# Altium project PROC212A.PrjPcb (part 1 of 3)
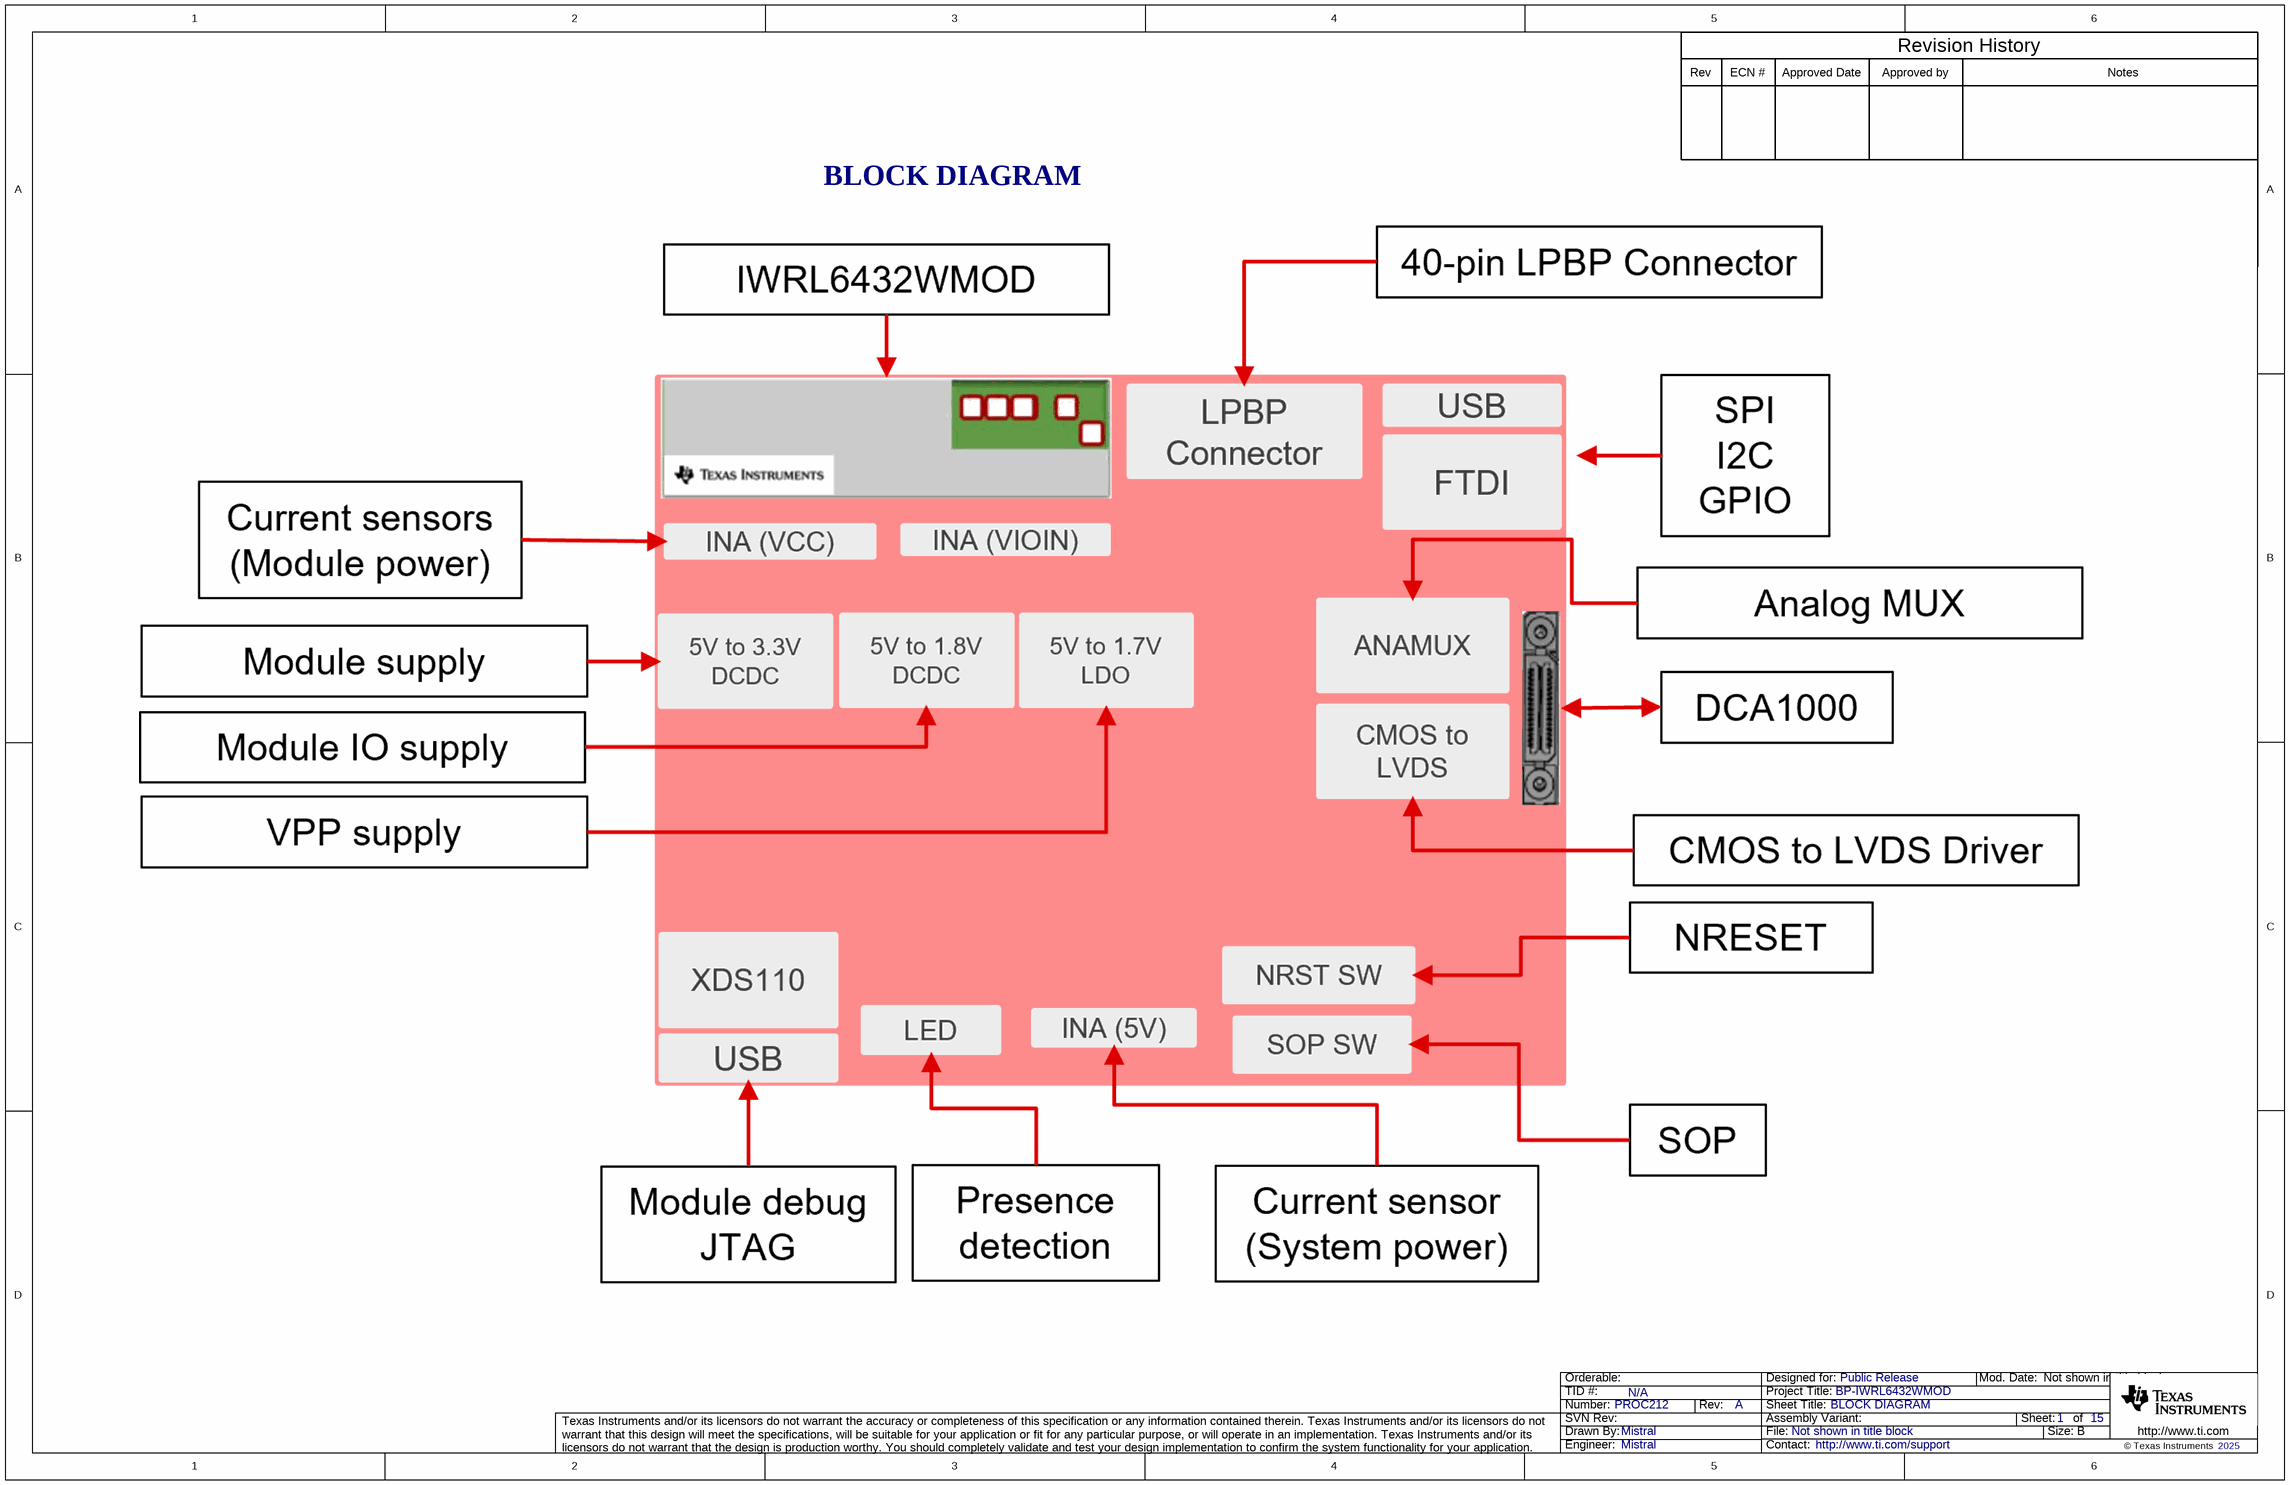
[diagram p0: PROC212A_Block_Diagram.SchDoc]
CopyrightYear: 2025; PCB_Layout: Mistral; PCB_Rev: A; PRJ_Customer: Public Release; PRJ_Engineer: Mistral; PRJ_Number: PROC212; PRJ_Title: BP-IWRL6432WMOD; SCH_Rev: A; TechSupport: http://www.ti.com/support; TID: N/A
15 sheets, 425 parts. Net scope: flat (ports and power ports of the same name join across sheets).
Board file: PROC212A_PCB.PcbDoc
Sheets:
  PROC212A_Block_Diagram.SchDoc
  PROC212A_MUX_Block_Diagram.SchDoc
  PROC212A_Table_Of_Contents.SchDoc
  PROC212A_BP_MMWAVE_MODULE.SchDoc
  PROC212A_USB_DC_JACK_PWR_Switch.SchDoc
  PROC212A_DC_Regulators.SchDoc
  PROC212A_ANALOG_MUX_LVDS_DRIVER.SchDoc
  PROC212A_ANALOG_MUX_SPI.SchDoc
  PROC212A_ANALOG_JTAG_MUX, CAN & SOP_CTRL.SchDoc
  PROC212A_Current_sensors_EPROM.SchDoc
  PROC212A_XDS110_Interface.SchDoc
  PROC212A_FTDI.SchDoc
  PROC212A_Reset_SW_LED_&_PRESENCE_LED.SchDoc
  PROC212A_DCA1000_LP_BP_Connectors.SchDoc
  PROC212A_EVM_Hardware.SchDoc

## Sheet PROC212A_Block_Diagram.SchDoc: BLOCK DIAGRAM
size 431 x 279 mm; Date: Not shown in title block; ApprovedBy: Not shown in title block; CheckedBy: Not shown in title block; Author: Not shown in title block; CompanyName: Not shown in title block; DrawnBy: Mistral; Organization: Not shown in title block; Address1: Not shown in title block; Address2: Not shown in title block; Address3: Not shown in title block; Address4: Not shown in title block; DocumentNumber: 1; Revision: Use project parameter SCH_Rev; SheetNumber: 1; SheetTotal: 15; PageSetup: Record=PageOptions¦CenterHorizontal=True¦CenterVertical=True¦PrintScale=1.00¦XCorrection=1.00¦YCorrection=1.00¦PrintKind=0¦BorderSize=5000000¦LeftOffset=0¦BottomOffset=0¦Orientation=2¦PaperLength=1000¦PaperWidth=1000¦Scale=100¦PaperSource=15¦PrintQuality=600¦MediaType=1¦DitherType=10¦PaperKind=Letter¦PrintScaleMode=1

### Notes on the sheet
- Rev
- ECN #
- Approved Date
- Approved by
- Revision History
- Notes
- BLOCK DIAGRAM

## Sheet PROC212A_MUX_Block_Diagram.SchDoc: MUX BLOCK DIAGRAM
size 431 x 279 mm; Date: Not shown in title block; ApprovedBy: Not shown in title block; CheckedBy: Not shown in title block; Author: Not shown in title block; CompanyName: Not shown in title block; DrawnBy: Mistral; Engineer: Not shown in title block; Organization: Not shown in title block; Address1: Not shown in title block; Address2: Not shown in title block; Address3: Not shown in title block; Address4: Not shown in title block; DocumentNumber: 2; Revision: Use project parameter SCH_Rev; SheetNumber: 2; SheetTotal: 15; PageSetup: Record=PageOptions¦CenterHorizontal=True¦CenterVertical=True¦PrintScale=1.00¦XCorrection=1.00¦YCorrection=1.00¦PrintKind=0¦BorderSize=5000000¦LeftOffset=0¦BottomOffset=0¦Orientation=2¦PaperLength=1000¦PaperWidth=1000¦Scale=100¦PaperSource=15¦PrintQuality=600¦MediaType=1¦DitherType=10¦PaperKind=Letter¦PrintScaleMode=1
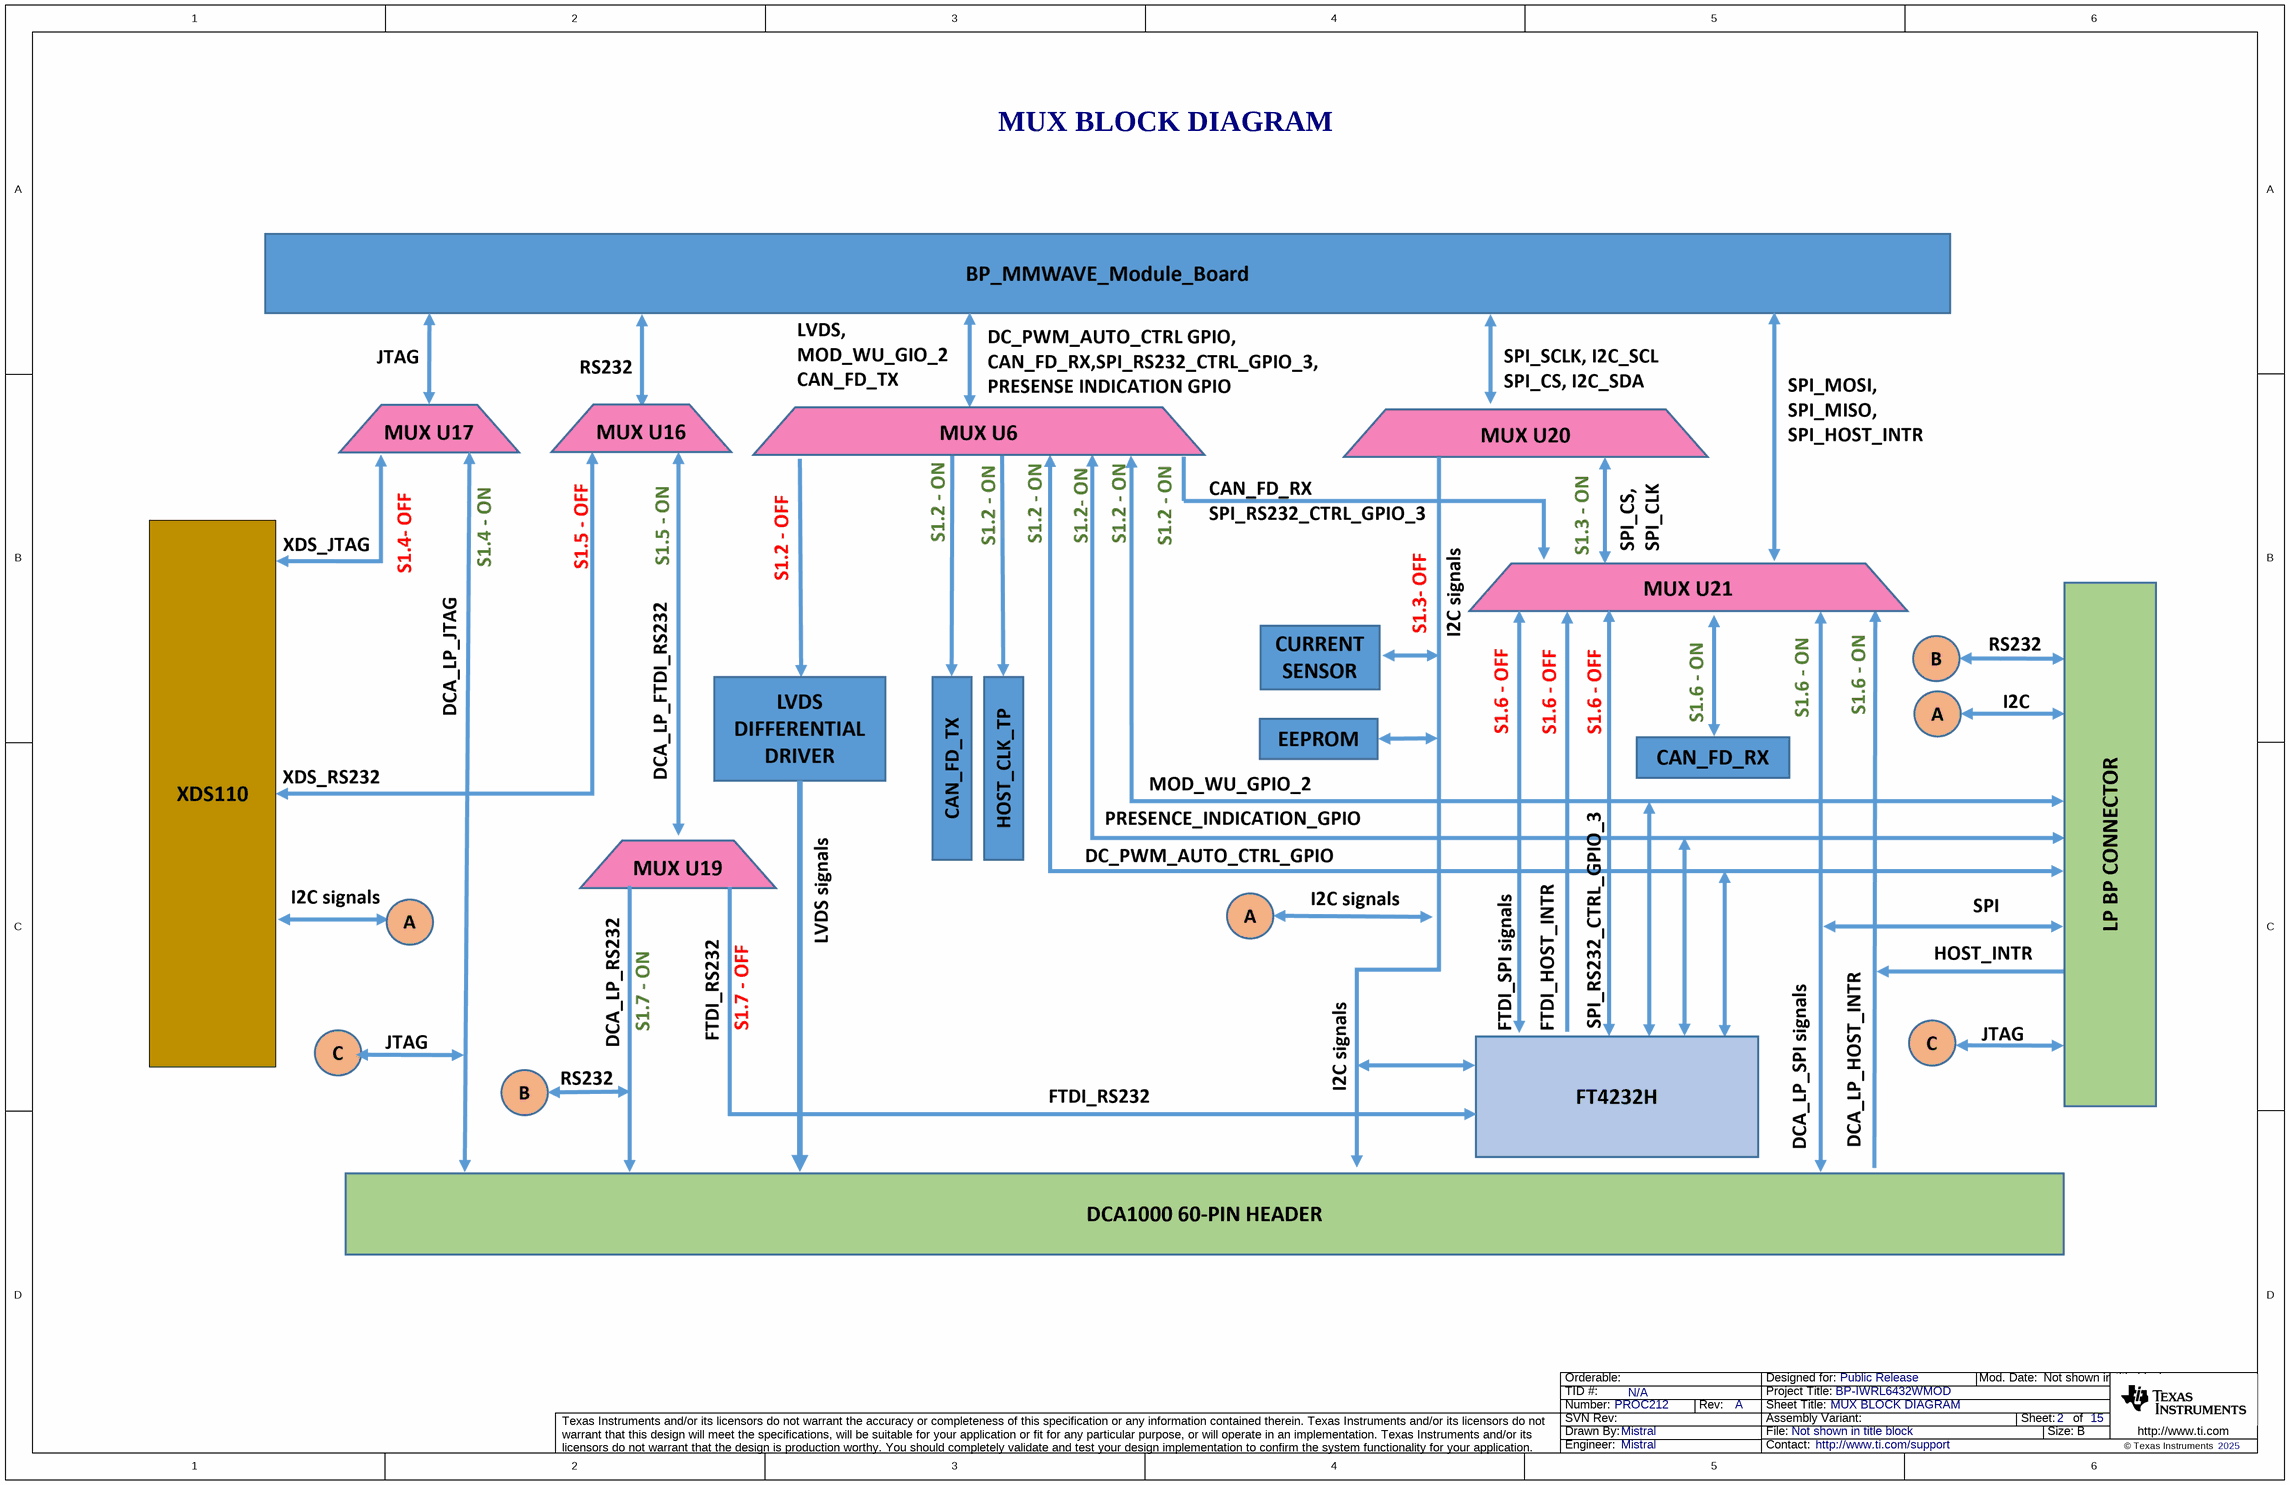
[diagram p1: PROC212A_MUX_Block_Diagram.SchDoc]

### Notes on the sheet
- MUX BLOCK DIAGRAM

## Sheet PROC212A_Table_Of_Contents.SchDoc: TABLE OF CONTENTS
size 431 x 279 mm; Date: Not shown in title block; ApprovedBy: Not shown in title block; CheckedBy: Not shown in title block; Author: Not shown in title block; CompanyName: Not shown in title block; DrawnBy: Mistral; Engineer: Not shown in title block; Organization: Not shown in title block; Address1: Not shown in title block; Address2: Not shown in title block; Address3: Not shown in title block; Address4: Not shown in title block; DocumentNumber: 3; Revision: Use project parameter SCH_Rev; SheetNumber: 3; SheetTotal: 15; PageSetup: Record=PageOptions¦CenterHorizontal=True¦CenterVertical=True¦PrintScale=1.00¦XCorrection=1.00¦YCorrection=1.00¦PrintKind=0¦BorderSize=5000000¦LeftOffset=0¦BottomOffset=0¦Orientation=2¦PaperLength=1000¦PaperWidth=1000¦Scale=100¦PaperSource=15¦PrintQuality=600¦MediaType=1¦DitherType=10¦PaperKind=Letter¦PrintScaleMode=1
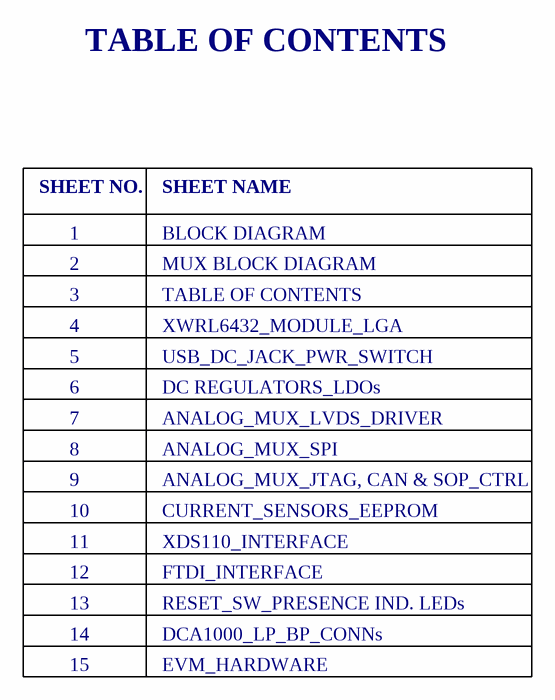
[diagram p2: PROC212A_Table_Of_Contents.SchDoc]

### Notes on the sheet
- TABLE OF CONTENTS
- SHEET NO.
- SHEET NAME
- 1
- 2
- 3
- BLOCK DIAGRAM
- MUX BLOCK DIAGRAM
- 4
- 5
- USB_DC_JACK_PWR_SWITCH
- XWRL6432_MODULE_LGA
- 7
- 8
- 6
- ANALOG_MUX_LVDS_DRIVER
- DC REGULATORS_LDOs
- ANALOG_MUX_SPI
- 9
- 10
- CURRENT_SENSORS_EEPROM
- ANALOG_MUX_JTAG, CAN & SOP_CTRL
- 11
- 12
- 13
- XDS110_INTERFACE
- FTDI_INTERFACE
- RESET_SW_PRESENCE IND. LEDs
- 14
- 15
- DCA1000_LP_BP_CONNs
- EVM_HARDWARE

## Sheet PROC212A_BP_MMWAVE_MODULE.SchDoc: BP_MMWAVE_MODULE_LGA
size 431 x 279 mm; Date: Not shown in title block; ApprovedBy: Not shown in title block; CheckedBy: Not shown in title block; Author: Not shown in title block; CompanyName: Not shown in title block; DrawnBy: Mistral; Engineer: Not shown in title block; Organization: Not shown in title block; Address1: Not shown in title block; Address2: Not shown in title block; Address3: Not shown in title block; Address4: Not shown in title block; DocumentNumber: 4; Revision: Use project parameter SCH_Rev; SheetNumber: 4; SheetTotal: 15; PageSetup: Record=PageOptions¦CenterHorizontal=True¦CenterVertical=True¦PrintScale=1.00¦XCorrection=1.00¦YCorrection=1.00¦PrintKind=0¦BorderSize=5000000¦LeftOffset=0¦BottomOffset=0¦Orientation=2¦PaperLength=1000¦PaperWidth=1000¦Scale=100¦PaperSource=15¦PrintQuality=600¦MediaType=1¦DitherType=10¦PaperKind=Letter¦PrintScaleMode=1
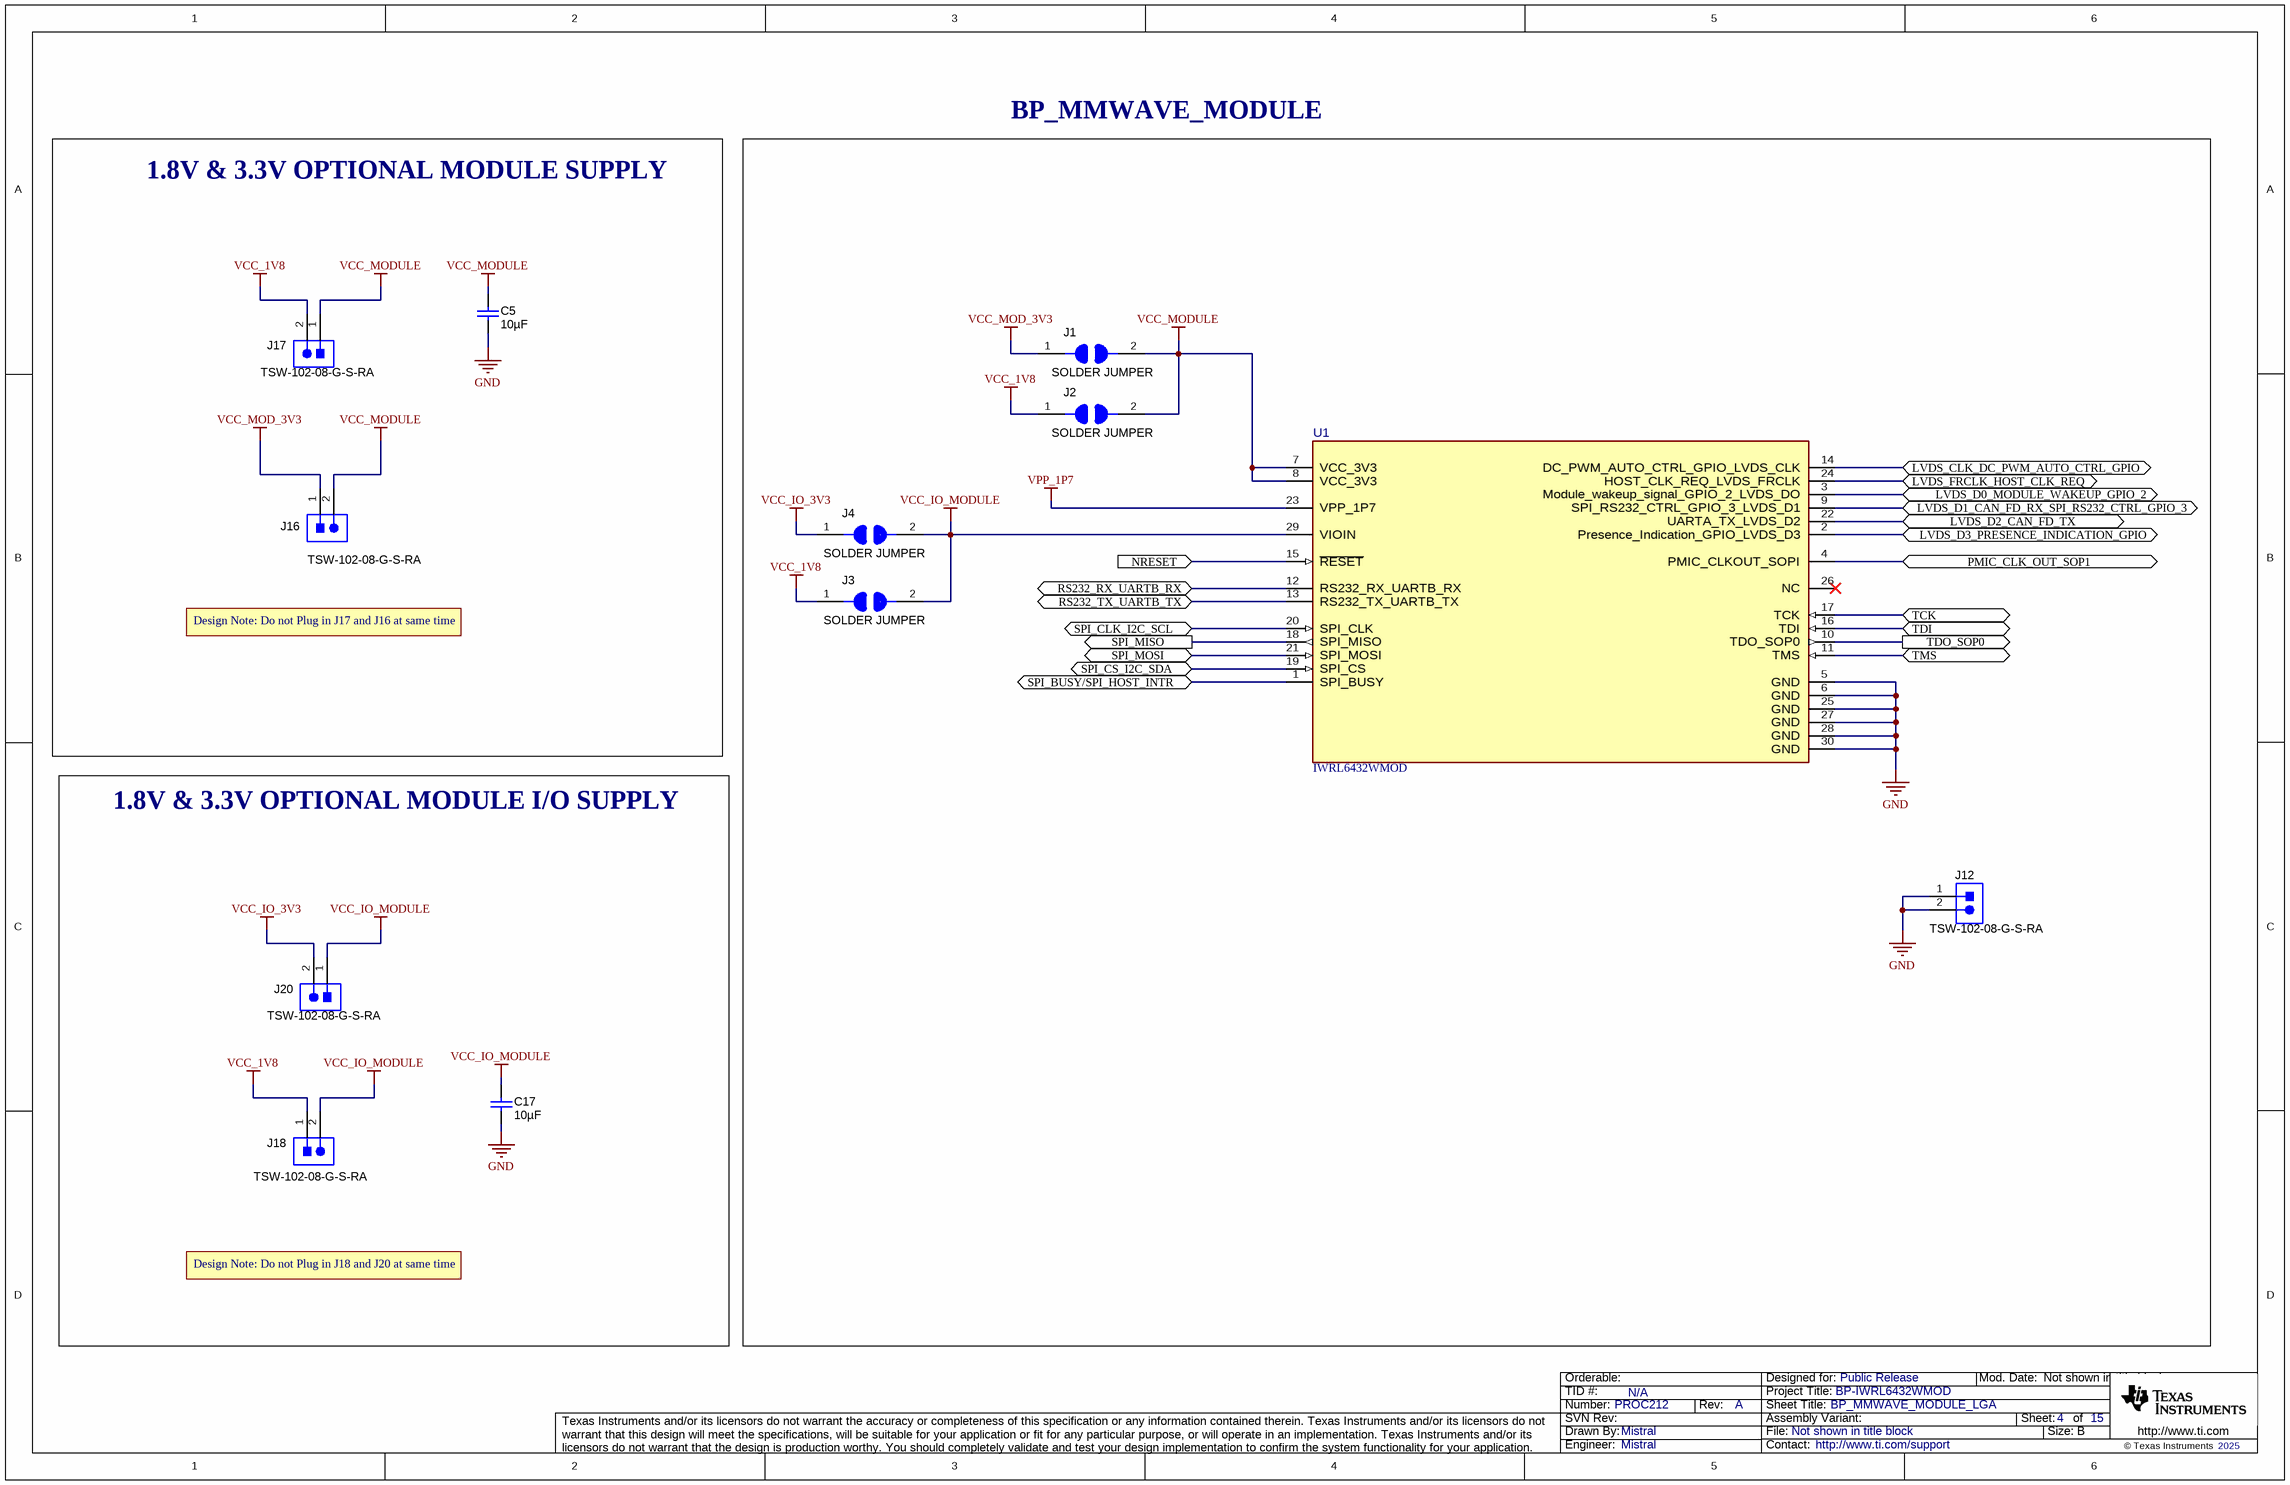
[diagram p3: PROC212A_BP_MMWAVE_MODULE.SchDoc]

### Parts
C5  Cap_F: 10µF  [0603]  (hidden comment: GRM188Z71A106MA73D)
C17  Cap_F: 10µF  [0603]  (hidden comment: GRM188Z71A106MA73D)
J1  SOLDER JUMPER  [SolderJumper]
J2  SOLDER JUMPER  [SolderJumper]
J3  SOLDER JUMPER  [SolderJumper]
J4  SOLDER JUMPER  [SolderJumper]
J12  TSW-102-08-G-S-RA  [TSW-102-08-G-S-RA]
J16  TSW-102-08-G-S-RA  [TSW-102-08-G-S-RA]
J17  TSW-102-08-G-S-RA  [TSW-102-08-G-S-RA]
J18  TSW-102-08-G-S-RA  [TSW-102-08-G-S-RA]
J20  TSW-102-08-G-S-RA  [TSW-102-08-G-S-RA]
U1  IWRL6432WMOD  [MBB0030A-MFG]

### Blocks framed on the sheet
1.8V & 3.3V OPTIONAL MODULE SUPPLY: C5 J16 J17
BP_MMWAVE_MODULE: J1-J4 J12 U1
1.8V & 3.3V OPTIONAL MODULE I/O SUPPLY: C17 J18 J20

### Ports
LVDS_CLK_DC_PWM_AUTO_CTRL_GPIO (bidir), LVDS_D0_MODULE_WAKEUP_GPIO_2 (bidir), LVDS_D1_CAN_FD_RX_SPI_RS232_CTRL_GPIO_3 (bidir), LVDS_D2_CAN_FD_TX (bidir), LVDS_D3_PRESENCE_INDICATION_GPIO (bidir), LVDS_FRCLK_HOST_CLK_REQ (bidir), NRESET (in), PMIC_CLK_OUT_SOP1 (bidir), RS232_RX_UARTB_RX (bidir), RS232_TX_UARTB_TX (bidir), SPI_BUSY/SPI_HOST_INTR (bidir), SPI_CLK_I2C_SCL (bidir), SPI_CS_I2C_SDA (bidir), SPI_MISO (out), SPI_MOSI (bidir), TCK (bidir), TDI (bidir), TDO_SOP0 (out), TMS (bidir)

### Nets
GND: C5.2 C17.2 J12.1 J12.2 U1.5(GND) U1.6(GND) U1.25(GND) U1.27(GND) U1.28(GND) U1.30(GND)
VCC_1V8: J2.1 J3.1 J17.2 J18.1
VCC_IO_3V3: J4.1 J20.2
VCC_IO_MODULE: C17.1 J3.2 J4.2 J18.2 J20.1 U1.29(VIOIN)
VCC_MOD_3V3: J1.1 J16.1
VCC_MODULE: C5.1 J1.2 J2.2 J16.2 J17.1 U1.7(VCC_3V3) U1.8(VCC_3V3)
VPP_1P7: U1.23(VPP_1P7)
LVDS_CLK_DC_PWM_AUTO_CTRL_GPIO: U1.14(DC_PWM_AUTO_CTRL_GPIO_LVDS_CLK) ; port LVDS_CLK_DC_PWM_AUTO_CTRL_GPIO
LVDS_D0_MODULE_WAKEUP_GPIO_2: U1.3(Module_wakeup_signal_GPIO_2_LVDS_DO) ; port LVDS_D0_MODULE_WAKEUP_GPIO_2
LVDS_D1_CAN_FD_RX_SPI_RS232_CTRL_GPIO_3: U1.9(SPI_RS232_CTRL_GPIO_3_LVDS_D1) ; port LVDS_D1_CAN_FD_RX_SPI_RS232_CTRL_GPIO_3
LVDS_D2_CAN_FD_TX: U1.22(UARTA_TX_LVDS_D2) ; port LVDS_D2_CAN_FD_TX
LVDS_D3_PRESENCE_INDICATION_GPIO: U1.2(Presence_Indication_GPIO_LVDS_D3) ; port LVDS_D3_PRESENCE_INDICATION_GPIO
LVDS_FRCLK_HOST_CLK_REQ: U1.24(HOST_CLK_REQ_LVDS_FRCLK) ; port LVDS_FRCLK_HOST_CLK_REQ
NRESET: U1.15(~{RESET}) ; port NRESET
PMIC_CLK_OUT_SOP1: U1.4(PMIC_CLKOUT_SOPI) ; port PMIC_CLK_OUT_SOP1
RS232_RX_UARTB_RX: U1.12(RS232_RX_UARTB_RX) ; port RS232_RX_UARTB_RX
RS232_TX_UARTB_TX: U1.13(RS232_TX_UARTB_TX) ; port RS232_TX_UARTB_TX
SPI_BUSY/SPI_HOST_INTR: U1.1(SPI_BUSY) ; port SPI_BUSY/SPI_HOST_INTR
SPI_CLK_I2C_SCL: U1.20(SPI_CLK) ; port SPI_CLK_I2C_SCL
SPI_CS_I2C_SDA: U1.19(SPI_CS) ; port SPI_CS_I2C_SDA
SPI_MISO: U1.18(SPI_MISO) ; port SPI_MISO
SPI_MOSI: U1.21(SPI_MOSI) ; port SPI_MOSI
TCK: U1.17(TCK) ; port TCK
TDI: U1.16(TDI) ; port TDI
TDO_SOP0: U1.10(TDO_SOP0) ; port TDO_SOP0
TMS: U1.11(TMS) ; port TMS

Not connected (* = marked no-connect by the designer): U1 26(NC)*

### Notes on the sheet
- Design Note: Do not Plug in J17 and J16 at same time
- Design Note: Do not Plug in J18 and J20 at same time

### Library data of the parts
C5 C17 = CMP-0007497-5: CAP, CERM, 10 uF, 10 V, +/- 20%, X7R, 0603; Manufacturer: MuRata; TaMin_C: -55°C; Polarized: N; SizeAreaWB_mm2: 4.68; Value1: Unknown; U/M: EA; Value: 10uF; TaMax_C: 125°C; SizeZ_mm: 1; SizeX_mm: 1.6; SizeY_mm: 0.8; Value2: 10V; SizeArea_mm2: 1.28; AEC Category: Q200
J1-J4 = CMP-0080367-2: Solder Jumper, SMT; Manufacturer: NA
J12 J16-J18 J20 = CMP-0055976-1: Header, 100mil, 2x1, Gold, R/A, TH; Manufacturer: Samtec; Cert_VDE: N; CNHeader: FALSE; Current_A: 6.3A; Green_Lifecycle: Active; Gender: Male; Cert_CSA: Y; Green_REACh: Passed; Voltage_V: 550V; Row_Count: 1; Pitch_mm: 2.54
U1 = CMP-0125875-3: Manufacturer: Texas Instruments; SizeZ_mm: 3.75mm; AEC Category: Q200; CompType: IC

## Sheet PROC212A_USB_DC_JACK_PWR_Switch.SchDoc: USB_DC_JACK_PWR_SWITCH
size 431 x 279 mm; Date: Not shown in title block; ApprovedBy: Not shown in title block; CheckedBy: Not shown in title block; Author: Not shown in title block; CompanyName: Not shown in title block; DrawnBy: Mistral; Engineer: Not shown in title block; Organization: Not shown in title block; Address1: Not shown in title block; Address2: Not shown in title block; Address3: Not shown in title block; Address4: Not shown in title block; DocumentNumber: 5; Revision: Use project parameter SCH_Rev; SheetNumber: 5; SheetTotal: 15; PageSetup: Record=PageOptions¦CenterHorizontal=True¦CenterVertical=True¦PrintScale=1.00¦XCorrection=1.00¦YCorrection=1.00¦PrintKind=0¦BorderSize=5000000¦LeftOffset=0¦BottomOffset=0¦Orientation=2¦PaperLength=1000¦PaperWidth=1000¦Scale=100¦PaperSource=15¦PrintQuality=600¦MediaType=1¦DitherType=10¦PaperKind=Letter¦PrintScaleMode=1
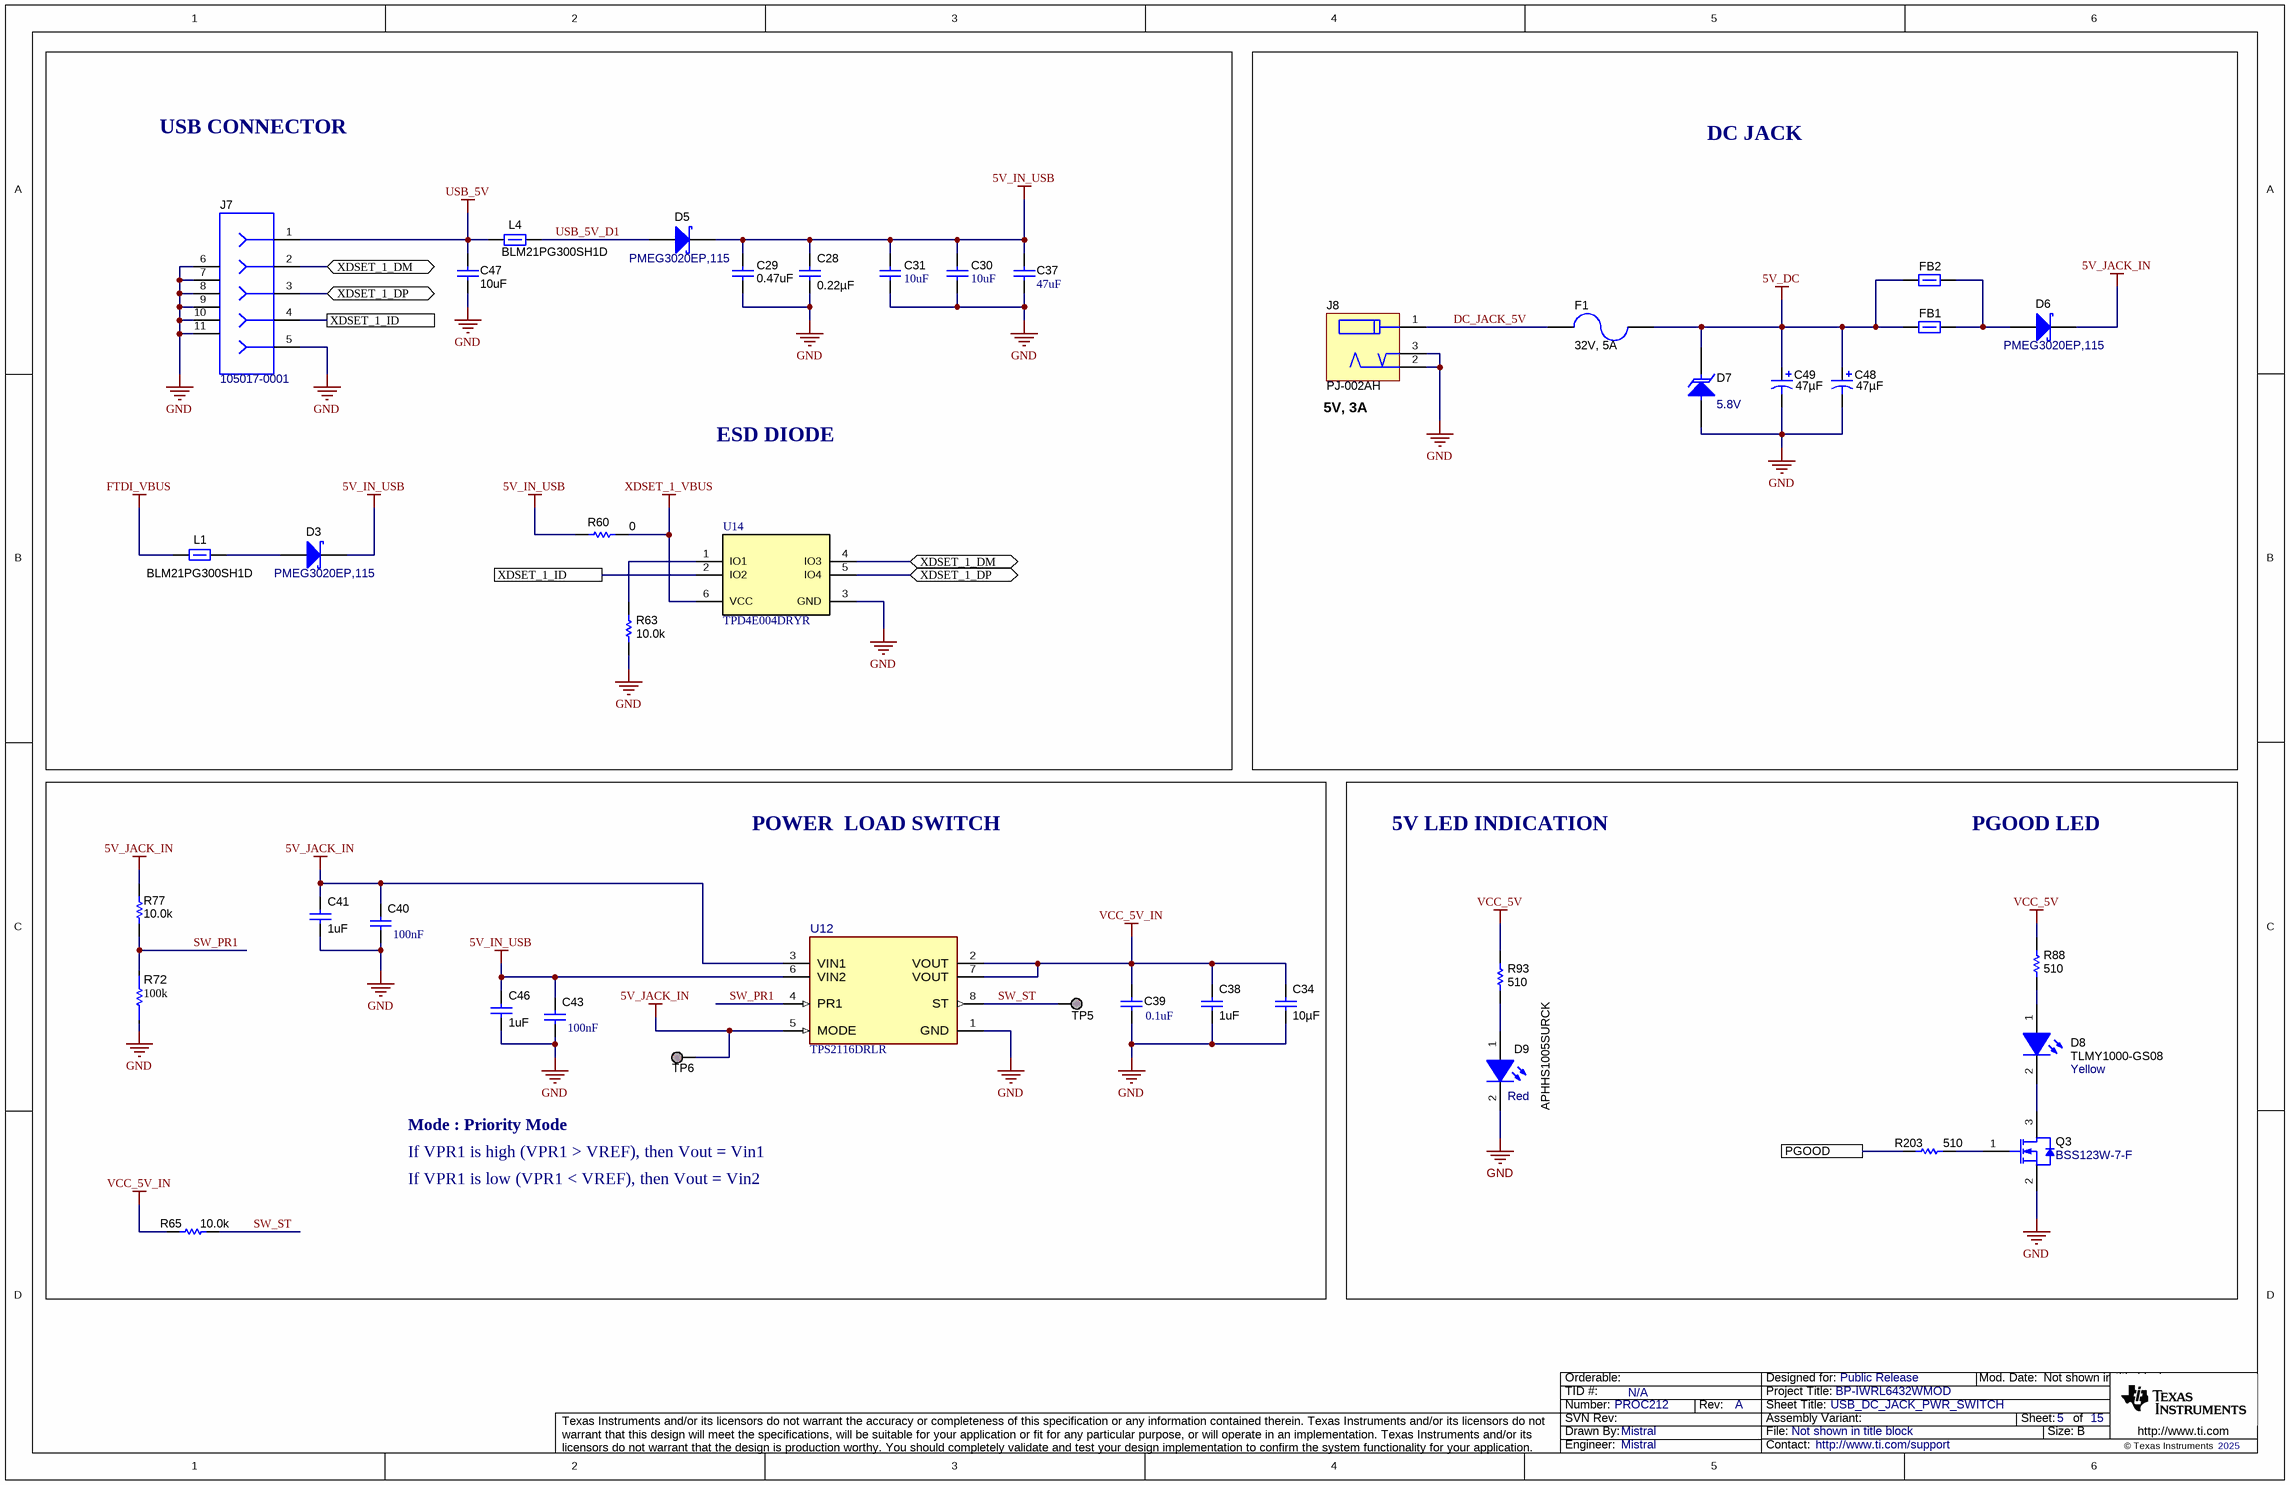
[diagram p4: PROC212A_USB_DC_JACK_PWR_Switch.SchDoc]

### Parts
C28  ValueDisplayed: 0.22µF  [0402L]  (hidden comment: GCM155R71C224KE02D)
C29  ValueDisplayed: 0.47uF  [0402L]  (hidden comment: GCM155C71A474KE36D)
C30  value 10uF  [0402S]  (hidden comment: GRM155R61A106ME11D)
C31  value 10uF  [0402S]  (hidden comment: GRM155R61A106ME11D)
C34  Cap_F: 10µF  [0603]  (hidden comment: GRM188Z71A106MA73D)
C37  ValueDisplayed: 47uF  [1206_180]  (hidden comment: GRM31CR61A476KE15L)
C38  ValueDisplayed: 1uF  [0402L]  (hidden comment: GRT155C81A105KE01D)
C39  ValueDisplayed: 0.1uF  [0402]  (hidden comment: GCM155R71H104KE02D)
C40  Cap_F: 100nF  [0402]  (hidden comment: GCM155R71H104KE02D)
C41  ValueDisplayed: 1uF  [0402L]  (hidden comment: GRT155C81A105KE01D)
C43  Cap_F: 100nF  [0402]  (hidden comment: GCM155R71H104KE02D)
C46  ValueDisplayed: 1uF  [0402L]  (hidden comment: GRT155C81A105KE01D)
C47  ValueDisplayed: 10uF  [0603S]  (hidden comment: GRT188R61A106KE13D)
C48  ValueDisplayed: 47µF  [3528-21]  (hidden comment: T491B476K010AT)
C49  ValueDisplayed: 47µF  [3528-21]  (hidden comment: T491B476K010AT)
D3  PMEG3020EP,115  [SOD-128]
D5  PMEG3020EP,115  [SOD-128]
D6  PMEG3020EP,115  [SOD-128]
D7  value 5.8V  [SMB]  (hidden comment: SZP6SMB6.8AT3G)
D8  TLMY1000-GS08  value Yellow  [TLMx1000_Yellow]
D9  APHHS1005SURCK  value Red  [APHHS1005_Red]
F1  32V, 5A  [1206]
FB1  BLM21PG300SH1D  [0805_HV]  (value not drawn)
FB2  BLM21PG300SH1D  [0805_HV]  (value not drawn)
J7  105017-0001  [CONN_105017-0001]
J8  PJ-002AH  [CUI_PJ-002AH]
L1  BLM21PG300SH1D  [0805]
L4  BLM21PG300SH1D  [0805]
Q3  BSS123W-7-F  [SOT-323]
R60  ValueDisplayed: 0  [0603]  (hidden comment: MCT06030Z0000ZP500)
R63  ValueDisplayed: 10.0k  [0402L]  (hidden comment: CRCW040210K0FKED)
R65  ValueDisplayed: 10.0k  [0402L]  (hidden comment: CRCW040210K0FKED)
R72  Res_ohm: 100k  [FP-CRCW0402100KFKEDC_0402-IPC_B]  (hidden comment: CRCW0402100KFKEDC)
R77  ValueDisplayed: 10.0k  [0402L]  (hidden comment: CRCW040210K0FKED)
R88  ValueDisplayed: 510  [0402L]  (hidden comment: ERJ-2GEJ511X)
R93  ValueDisplayed: 510  [0402L]  (hidden comment: ERJ-2GEJ511X)
R203  ValueDisplayed: 510  [0402L]  (hidden comment: ERJ-2GEJ511X)
TP5  TESTPOINT  [TP_25MIL-SMT]  (value not drawn)  (no BOM)
TP6  TESTPOINT  [TP_25MIL-SMT]  (value not drawn)  (no BOM)
U12  TPS2116DRLR  [DRL0008A-MFG]
U14  TPD4E004DRYR  [DRY0006A]

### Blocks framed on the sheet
DC JACK: C48 C49 D6 D7 F1 FB1 FB2 J8
POWER  LOAD SWITCH: C34 C38-C41 C43 C46 R65 R72 R77 TP5 TP6 U12

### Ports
PGOOD, XDSET_1_DM (bidir), XDSET_1_DP (bidir), XDSET_1_ID

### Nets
5V_DC: C48.1(+) C49.1(+) D7.1(K) F1.1 FB1.1 FB2.1
5V_IN_USB: C28.2 C29.1 C30.1 C31.2 C37.1 C43.2 C46.1 D3.1(K) D5.1(K) R60.2 U12.6(VIN2)
5V_JACK_IN: C40.2 C41.1 D6.1(K) R77.1 TP6.1 U12.3(VIN1) U12.5(MODE)
FTDI_VBUS: L1.1
GND: C28.1 C29.2 C30.2 C31.1 C34.2 C37.2 C38.2 C39.2 C40.1 C41.2 C43.1 C46.2 C47.1 C48.2(-) C49.2(-) D7.2(A) D9.2(K) J7.5 J7.6 J7.7 J7.8 J7.9 J7.10 J7.11 J8.2 J8.3 Q3.2(S) R63.1 R72.1 U12.1(GND) U14.3(GND)
USB_5V: C47.2 J7.1 L4.1
VCC_5V: R88.2 R93.2
VCC_5V_IN: C34.1 C38.1 C39.1 R65.2 U12.2(VOUT) U12.7(VOUT)
XDSET_1_VBUS: R60.1 U14.6(VCC)
DC_JACK_5V: F1.2 J8.1
PGOOD: R203.1 ; port PGOOD
SW_PR1: R72.2 R77.2 U12.4(PR1)
SW_ST: R65.1 TP5.1 U12.8(ST)
USB_5V_D1: D5.2(A) L4.2
XDSET_1_DM: J7.2 U14.4(IO3) ; port XDSET_1_DM
XDSET_1_DP: J7.3 U14.5(IO4) ; port XDSET_1_DP
XDSET_1_ID: J7.4 U14.2(IO2) ; port XDSET_1_ID
NetD3_2: D3.2(A) L1.2
NetD6_2: D6.2(A) FB1.2 FB2.2
NetD8_1: D8.1(A) R88.1
NetD8_2: D8.2(K) Q3.3(D)
NetD9_1: D9.1(A) R93.1
NetQ3_1: Q3.1(G) R203.2
NetR63_2: R63.2 U14.1(IO1)

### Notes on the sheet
- USB CONNECTOR
- ESD DIODE
- (near J8) 5V, 3A
- 5V LED INDICATION
- PGOOD LED
- Mode : Priority Mode
- If VPR1 is high (VPR1 > VREF), then Vout = Vin1
- If VPR1 is low (VPR1 < VREF), then Vout = Vin2

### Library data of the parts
C28 = CMP-0078265-1: CAP, CERM, 0.22 µF, 16 V,+/- 10%, X7R, AEC-Q200 Grade 1, 0402; Manufacturer: MuRata; TaMin_C: -55°C; Polarized: N; SizeAreaWB_mm2: 3; U/M: EA; Value: 0.22uF; TaMax_C: 125°C; SizeZ_mm: 0.6; SizeX_mm: 1; SizeY_mm: 0.5; Cap_Case: 0402; Value2: 16V; CompType: Capacitor; AEC Qualified: Y; Cap_F: 220nF; AEC Category: Q200
C29 = CMP-0064967-2: CAP, CERM, 0.47 uF, 10 V,+/- 10%, X7S, 0402; Manufacturer: MuRata; Polarized: N; Value: 0.47uF; U/M: EA; Cap_F: 470nF; Value1: Unknown; VDC_V: 10V; TaMin_C: -55°C; TaMax_C: 125°C; Cap_Case: 0402; SizeArea_mm2: 0.5; SizeAreaWB_mm2: 3; SizeX_mm: 1; SizeZ_mm: 0.6; AEC Category: Q200
C30 C31 = CMP-0006564-3: CAP, CERM, 10 uF, 10 V, +/- 20%, X5R, 0402; Manufacturer: MuRata; AEC Category: Q200; Cap_Case: 0402; Cap_F: 10µF; Polarized: N; SizeArea_mm2: 0.5; SizeAreaWB_mm2: 3; SizeX_mm: 1; SizeZ_mm: 0.6; TaMax_C: 85°C; TaMin_C: -55°C; U/M: EA; Value1: Unknown; Value2: 10V
C34 = CMP-0007497-5: as C5 on sheet PROC212A_BP_MMWAVE_MODULE
C37 = CMP-0008944-2: CAP, CERM, 47 uF, 10 V, +/- 10%, X5R, 1206; Manufacturer: MuRata; TaMin_C: -55°C; Polarized: N; SizeAreaWB_mm2: 10.92; Value1: Unknown; U/M: EA; Value: 47uF; TaMax_C: 85°C; SizeZ_mm: 1.8; SizeX_mm: 3.2; SizeY_mm: 1.6; Cap_Case: 1206; Value2: 10V; SizeArea_mm2: 5.12; Cap_F: 47µF; AEC Category: Q200
C38 C41 C46 = CMP-0006272-2: CAP, CERM, 1 uF, 10 V, +/- 10%, X6S, 0402; Manufacturer: TDK; Polarized: N; Value: 1uF; U/M: EA; Cap_F: 1µF; Value1: Unknown; VDC_V: 16V; TempCo: X5R; TaMin_C: -55°C; TaMax_C: 85°C; Cap_Case: 0402; SizeArea_mm2: 0.5; SizeAreaWB_mm2: 3; SizeX_mm: 1; SizeZ_mm: 0.6; AEC Category: Q200
C39 = CMP-0006356-2: CAP, CERM, 0.1 uF, 50 V, +/- 10%, X7R, AEC-Q200 Grade 1, 0402; Manufacturer: MuRata; TaMin_C: -55°C; Polarized: N; SizeAreaWB_mm2: 3; Value1: Unknown; U/M: EA; Value: 0.1uF; TaMax_C: 125°C; SizeZ_mm: 0.6; SizeX_mm: 1; SizeY_mm: 0.5; Value2: 50V; AEC Qualified: Y; Cap_F: 100nF; AEC Category: Q200
C40 C43 = CMP-0006356-2: CAP, CERM, 0.1 uF, 50 V, +/- 10%, X7R, AEC-Q200 Grade 1, 0402; Manufacturer: MuRata; AEC Qualified: Y; SizeZ_mm: 0.6; VDC_V: 50V; AEC Category: Q200; AEC Grade: 1; Polarized: N; SizeArea_mm2: 0.5; SizeAreaWB_mm2: 3; TaMax_C: 125°C; TaMin_C: -55°C; U/M: EA; Value1: Unknown; Value: 0.1uF
C47 = CMP-0007497-5: CAP, CERM, 10 uF, 10 V, +/- 10%, X5R, 0603; Manufacturer: MuRata; Polarized: N; Value: 10uF; U/M: EA; Cap_F: 10µF; Tolerance_%: 20%; Value1: Unknown; VDC_V: 10V; TempCo: X7R; TaMin_C: -55°C; TaMax_C: 125°C; Cap_Case: 0603; SizeArea_mm2: 1.28; SizeAreaWB_mm2: 4.68; SizeX_mm: 1.6; SizeY_mm: 0.8; SizeZ_mm: 1; AEC Category: Q200
C48 C49 = CMP-0078216-1: CAP, TA, 47 µF, 10 V, +/- 10%, SMD; Manufacturer: Kemet; TaMin_C: -55°C; Polarized: Y; SizeAreaWB_mm2: 17.1; Value: 47uF; TaMax_C: 125°C; SizeZ_mm: 2.1; SizeX_mm: 3.5; SizeY_mm: 2.8; Value2: 10V; SizeArea_mm2: 9.8; CompType: Capacitor; AEC Qualified: N; AEC Category: Q200
D3 D5 D6 = CMP-0078758-2: Diode, Schottky, 30 V, 2 A, AEC-Q101, SOD-128; Manufacturer: Nexperia; Value2: 0.36V; SizeAreaWB_mm2: 19.6; Io_A: 2A; Value: 30V; AEC Qualified: Y; TJmax_C: 150°C; SizeX_mm: 4.6; AEC Category: Q101; SizeY_mm: 2.5; SizeArea_mm2: 11.5; Vf_V: 3.6dV; SizeZ_mm: 1.1
D7 = CMP-0078243-3: Diode, TVS, Uni, 5.8 V, 10.5 Vc, AEC-Q101, SMB; Manufacturer: Littelfuse; SizeAreaWB_mm2: 44.156; Value1: 0.55W; RJA_CperW: 226; SizeZ_mm: 2.6; SizeX_mm: 5.6; SizeY_mm: 3.81; SizeArea_mm2: 21.336; AEC Qualified: Y; AEC Category: Q101; Vc: 10.5V
D8 = CMP-0078196-2: LED, Yellow, SMD; Manufacturer: Vishay-Semiconductor; Tjmax_C: 120°C; SizeAreaWB_mm2: 4.68; Vr_V: 6V; Power_TotalModule: 40mW; Angle: 160; SizeArea_mm2: 1.28; Ir_A: 10µA; SizeZ_mm: 0.65; Io_A: 2mA; Vf_V: 1.8V; SizeY_mm: 0.8; Value1: .04W; SizeX_mm: 1.6; Type: AlInGaP
D9 = CMP-0067681-2: LED, Red, SMD; Manufacturer: Kingbright; Vf_V: 1.95V; SizeAreaWB_mm2: 3.0; Tjmax_C: 85°C; SizeX_mm: 1.0; Io_A: 20mA; SizeArea_mm2: 0.5; Vr_V: 5V; Value1: 0.075W; SizeZ_mm: 0.6; Angle: 120.0; Ir_A: 10µA; Power_TotalModule: 75mW
F1 = CMP-0003458-2: Fuse, 5 A, 32VAC/VDC, SMD; Manufacturer: Littelfuse; PartNumber: 0440005.WR; SizeAreaWB_mm2: 10.92; Interrupt_AC: 50A; SizeZ_mm: 1.35; SizeX_mm: 3.2; SizeY_mm: 1.6; SizeArea_mm2: 5.12; Rtyp_Ohm: 0.012; MeltingTyp: 4.761
FB1 = CMP-0003364-1: Ferrite Bead, 30 ohm @ 100 MHz, 4 A, 0805; Manufacturer: MuRata; ZTyp@100MHz_Ohm: 30; SizeAreaWB_mm2: 6.75; DCR_ohm: 0.014; Value1: 0.014 ohm; Value: 30 ohm; Imax_A: 4A; SizeZ_mm: 1.45; SizeX_mm: 2; SizeY_mm: 1.25; SizeArea_mm2: 2.5; INSTALLATION: DNP
FB2 = CMP-0003364-1: Ferrite Bead, 30 ohm @ 100 MHz, 4 A, 0805; Manufacturer: MuRata; ZTyp@100MHz_Ohm: 30; SizeAreaWB_mm2: 6.75; DCR_ohm: 0.014; Value1: 0.014 ohm; Value: 30 ohm; Imax_A: 4A; SizeZ_mm: 1.45; SizeX_mm: 2; SizeY_mm: 1.25; SizeArea_mm2: 2.5
J7 = CMP-0055293-1: Connector, Receptacle, Micro-USB Type B, R/A, Bottom Mount SMT; Manufacturer: Molex; CNHeader: FALSE; CompType: USB; CT: TRUE; Gender: Female; Green_Lifecycle: Active; Green_REACh: Passed
J8 = CMP-0078270-1: DC POWER JACK, R/A, TH; Manufacturer: CUI Inc.; Gender: Female; Cert_UL: Y; Current_A: 5A; Voltage_V: 4.5-5.5V; Green_REACh: Incomplete; Green_Lifecycle: Not Set
L1 L4 = CMP-0003364-1: Ferrite Bead, 30 ohm @ 100 MHz, 4 A, 0805; Manufacturer: MuRata; ZTyp@100MHz_Ohm: 30; SizeAreaWB_mm2: 6.75; DCR_ohm: 14m; Value1: 0.014 ohm; Value: 30 ohm; Imax_A: 4A; SizeZ_mm: 1.45; SizeX_mm: 2; SizeY_mm: 1.25; SizeArea_mm2: 2.5
Q3 = CMP-0000948-2: MOSFET, N-CH, 100 V, 0.17 A, SOT-323; Alternate Manufacturer: None; Manufacturer: Diodes Inc.; SizeZ_mm: 1.1; ChType: N; Value1: 1; VdsMax_V: 100V; SizeX_mm: 2.2; Vgs_V: 20V; Value: 100V; Rdson45_ohm: 10; SizeArea_mm2: 4.84; AEC Category: Q101; IdsMax_A: 1.7dA; SizeAreaWB_mm2: 10.24; U/M: EA
R60 = CMP-0025884-3: RES, 0, 5%, 0.125 W, 0603; Manufacturer: Vishay/Beyschlag; Power_W: 125mW; TempCo: ppm/C; Value_Code: 0000; U/M: EA; Value: 0; EIA_Code: E24; SizeX_mm: 1.6; SizeY_mm: 0.8; SizeZ_mm: 1; Value2: 0.125W; SizeArea_mm2: 1.28; AEC Qualified: N; AEC Category: Q200
R63 R65 R77 = CMP-0025958-3: RES, 10.0 k, 1%, 0.063 W, AEC-Q200 Grade 0, 0402; Manufacturer: Vishay-Dale; Power_W: 63mW; TempCo: 100 ppm/C; Value_Code: 10k0; Value: 10.0k; EIA_Code: E96; Res_ohm: 10k; SizeX_mm: 1; SizeY_mm: 0.5; SizeZ_mm: 0.6; Value2: 0.063W; AEC Qualified: Y; VDC_V: 50V; AEC Category: Q200; AEC Grade: 0
R72 = CMP-0092204-1: 100 kOhms ±1% 0.063W, 1/16W Chip Resistor 0402 (1005 Metric)  Thick Film; Manufacturer: Vishay; Power_W: 63mW; AEC Qualified: No; TempCo: 100ppm/°C; SizeZ_mm: 0.35mm; VDC_V: 50V; Value: 100k
R88 R93 R203 = CMP-0078212-1: RES, 510, 5%, 0.1 W, AEC-Q200 Grade 0, 0402; Manufacturer: Panasonic; Value_Code: 510R; SizeArea_mm2: 0.5; AEC Qualified: Y; AEC Category: Q200; Value: 510; SizeZ_mm: 0.6; EIA_Code: E24; TempCo: 200 ppm/C; AEC Grade: 0; Power_W: 100mW; VDC_V: 50V; Value2: 0.1W; U/M: EA; SizeX_mm: 1
TP5 TP6 = CMP-0078143-3: TEST POINT.  No entry in BOM.
U12 = CMP-0088593-2: 1.6 V to 5 V, 2.5-A Low IQ Power Mux With Manual and Automatic Switchover; Manufacturer: Texas Instruments; Max Supply Voltage: 5.5V; TaMax_C: +125°C; Output Voltage: 0-5.5V; CompType: IC; Min Supply Voltage: 1.6V; TaMin_C: -55°C; SizeZ_mm: 0.6mm; AEC Category: Q200; Nominal Supply Current: 0.5-1uA; Number Of Outputs: 1; Standoff Height: 0mm; AEC Qualified: No
U14 = CMP-0043115-3: 4-Channel ESD Protection Array for High-Speed Data Interfaces, DRY0006A (USON-6); Manufacturer: Texas Instruments; IO Leakage Current(nA): 1; USB High Speed: TRUE; IO Capacitance(Typ)(pF): 1.6; Eco-Plan: Green (RoHS & no Sb/Br); IEC 61000-4-2 Contact(+/- kV): 8; Breakdown Voltage(Min)(V): 6; IEC 61000-4-2 Air-Gap(+/- kV): 12; AEC Category: Q200; AEC Qualified: N; CompType: IC; SizeAreaWB_mm2: 4.9; SizeArea_mm2: 1.45; SizeX_mm: 1.0; SizeZ_mm: 0.6; Rating: Catalog

## Sheet PROC212A_DC_Regulators.SchDoc: DC_REGULATOR_LDO_SECTION
size 431 x 279 mm; Date: Not shown in title block; ApprovedBy: Not shown in title block; CheckedBy: Not shown in title block; Author: Not shown in title block; CompanyName: Not shown in title block; DrawnBy: Mistral; Engineer: Not shown in title block; Organization: Not shown in title block; Address1: Not shown in title block; Address2: Not shown in title block; Address3: Not shown in title block; Address4: Not shown in title block; DocumentNumber: 6; Revision: Use project parameter SCH_Rev; SheetNumber: 6; SheetTotal: 15; PageSetup: Record=PageOptions¦CenterHorizontal=True¦CenterVertical=True¦PrintScale=1.00¦XCorrection=1.00¦YCorrection=1.00¦PrintKind=0¦BorderSize=5000000¦LeftOffset=0¦BottomOffset=0¦Orientation=2¦PaperLength=1000¦PaperWidth=1000¦Scale=100¦PaperSource=15¦PrintQuality=600¦MediaType=1¦DitherType=10¦PaperKind=Letter¦PrintScaleMode=1
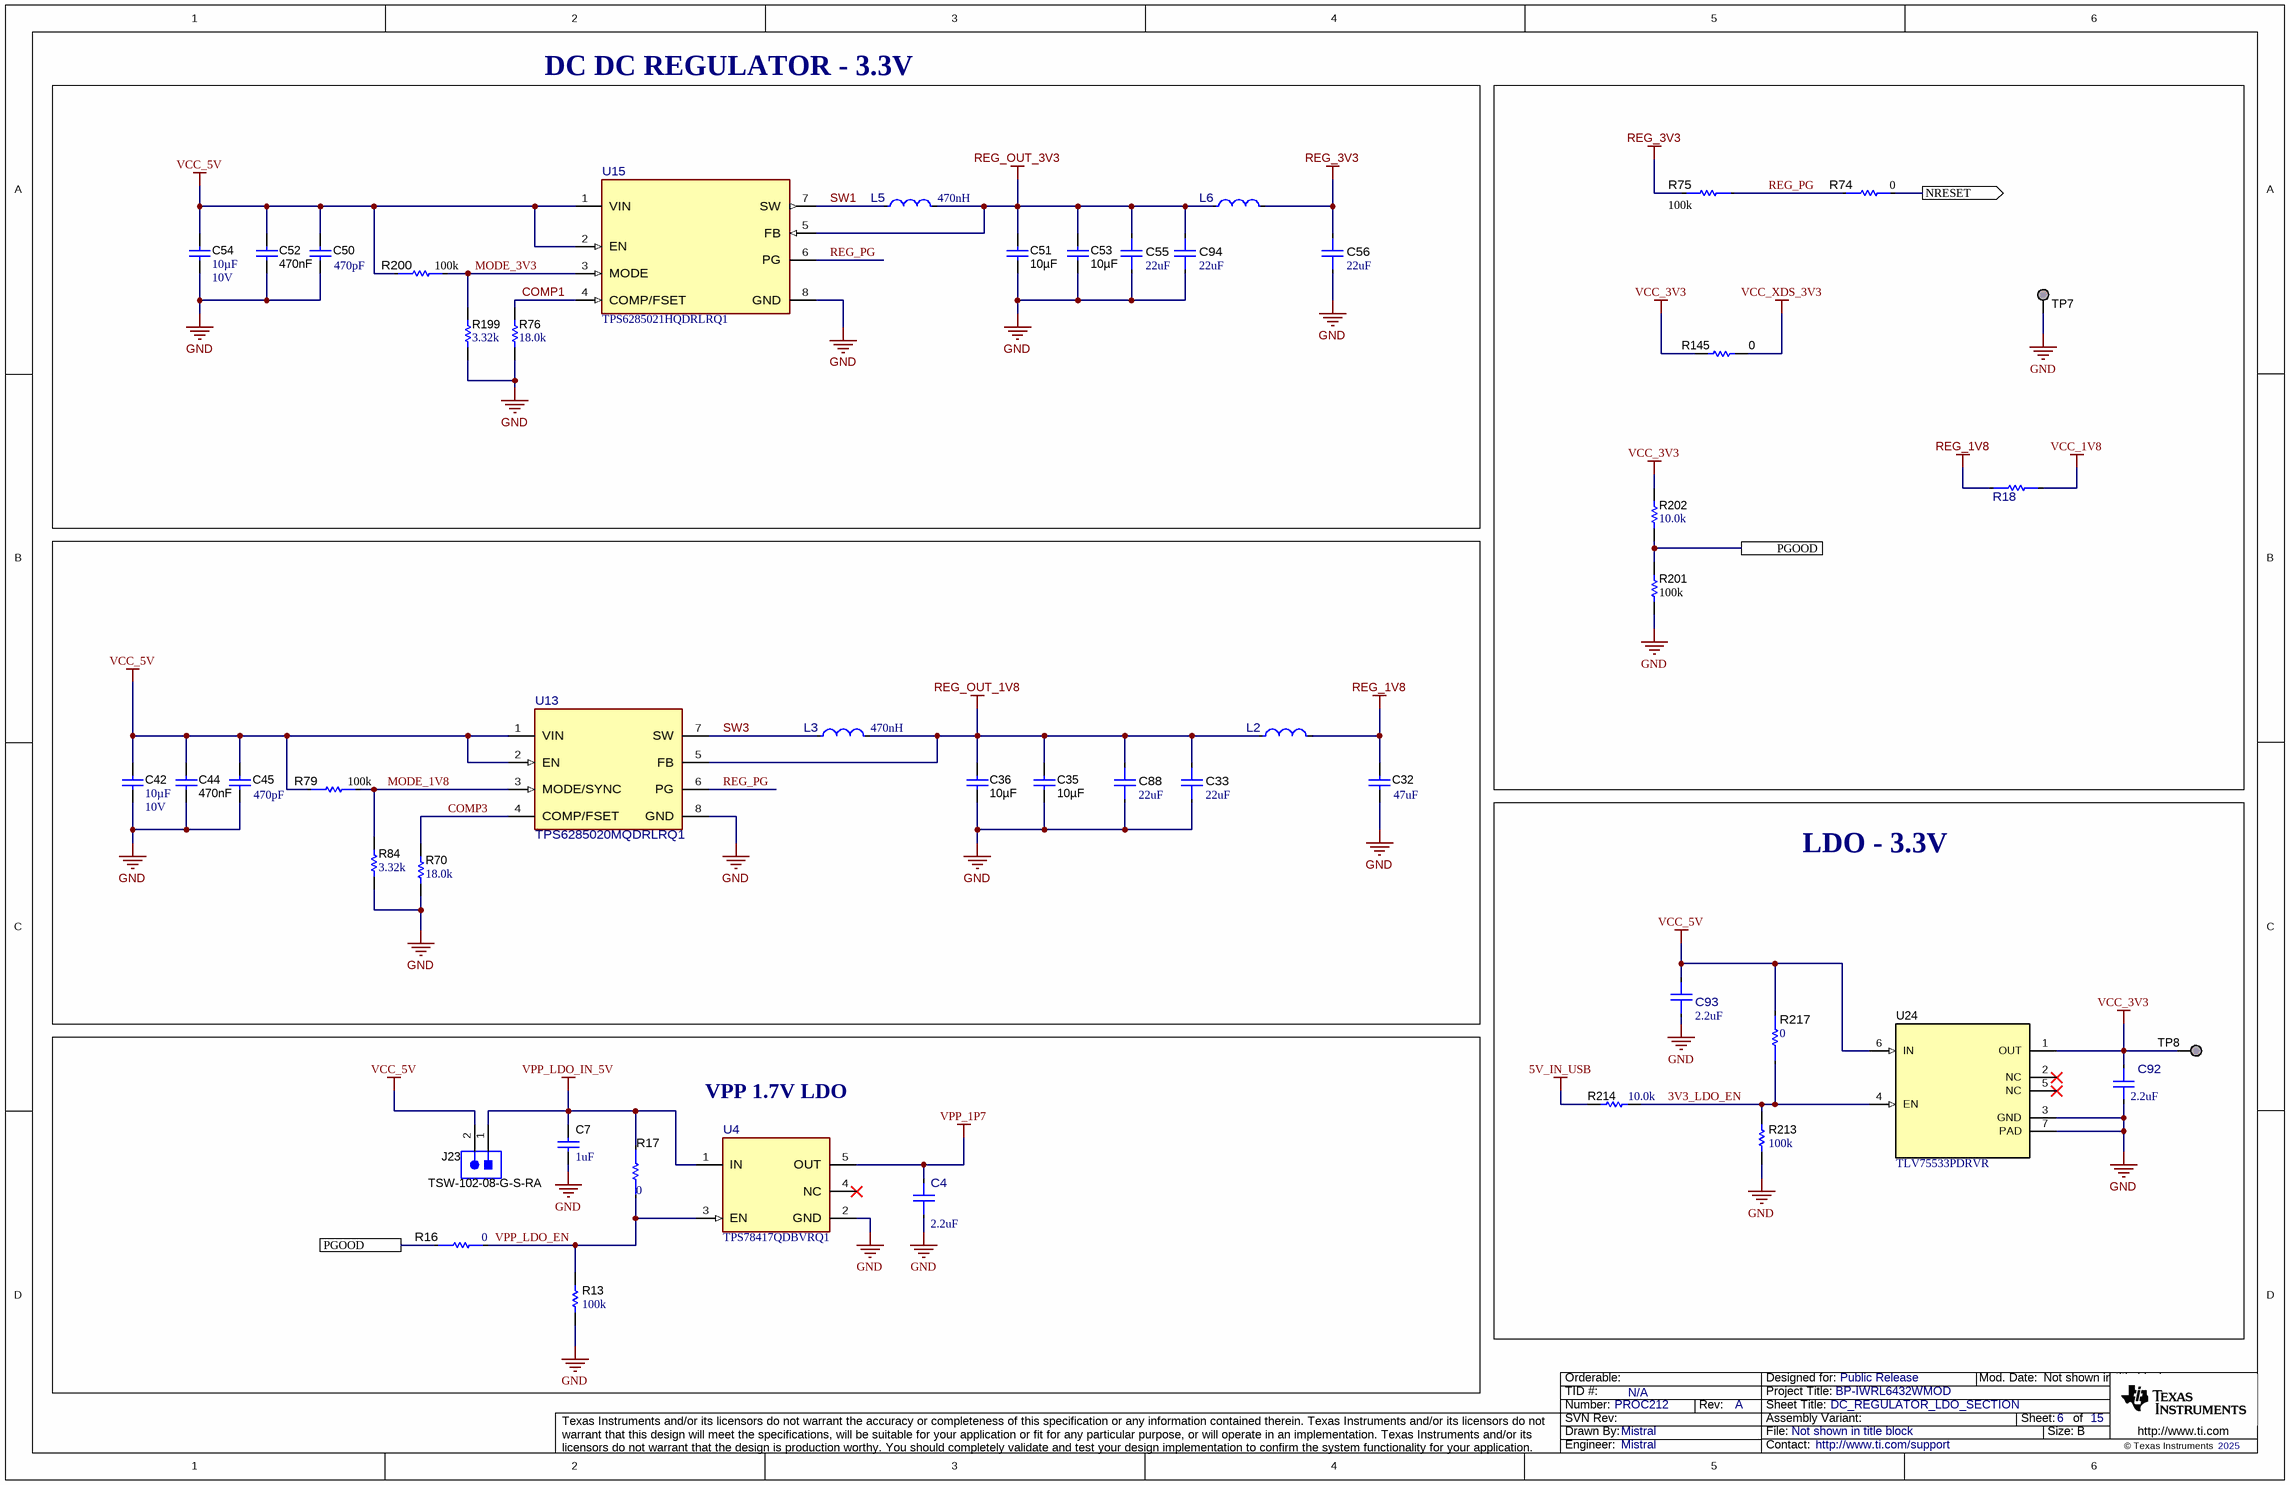
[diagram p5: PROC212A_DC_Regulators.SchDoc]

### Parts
C4  ValueDisplayed: 2.2uF  [FP-GRT155C71A225KE13D_0402-MFG]  (hidden comment: GRT155C71A225KE13D)
C7  ValueDisplayed: 1uF  [0402_070]  (hidden comment: GCM155C71A105KE38D)
C32  ValueDisplayed: 47uF  [1206_180]  (hidden comment: GRM31CR60J476ME19L)
C33  ValueDisplayed: 22uF  [FP-GRM31CR70J226ME19K_1206-MFG]  (hidden comment: GRM31CR70J226ME19K)
C35  Cap_F: 10µF  [0603]  (hidden comment: GRM188Z71A106MA73D)
C36  Cap_F: 10µF  [0603]  (hidden comment: GRM188Z71A106MA73D)
C42  Cap_F: 10µF  VDC_V: 10V  [0603_HV]  (hidden comment: GRM188Z71A106MA73D)
C44  Cap_F: 470nF  [0603S]  (hidden comment: GRM188R71C474KA88D)
C45  ValueDisplayed: 470pF  [0402L]  (hidden comment: GRM1555C1H471JA01D)
C50  ValueDisplayed: 470pF  [0402L]  (hidden comment: GRM1555C1H471JA01D)
C51  Cap_F: 10µF  [0603]  (hidden comment: GRM188Z71A106MA73D)
C52  Cap_F: 470nF  [0603S]  (hidden comment: GRM188R71C474KA88D)
C53  Cap_F: 10µF  [0603]  (hidden comment: GRM188Z71A106MA73D)
C54  Cap_F: 10µF  VDC_V: 10V  [0603_HV]  (hidden comment: GRM188Z71A106MA73D)
C55  ValueDisplayed: 22uF  [FP-GRM31CR70J226ME19K_1206-MFG]  (hidden comment: GRM31CR70J226ME19K)
C56  ValueDisplayed: 22uF  [FP-GRM31CR70J226ME19K_1206-MFG]  (hidden comment: GRM31CR70J226ME19K)
C88  ValueDisplayed: 22uF  [FP-GRM31CR70J226ME19K_1206-MFG]  (hidden comment: GRM31CR70J226ME19K)
C92  ValueDisplayed: 2.2uF  [FP-GRT155C71A225KE13D_0402-MFG]  (hidden comment: GRT155C71A225KE13D)
C93  ValueDisplayed: 2.2uF  [FP-GRT155C71A225KE13D_0402-MFG]  (hidden comment: GRT155C71A225KE13D)
C94  ValueDisplayed: 22uF  [FP-GRM31CR70J226ME19K_1206-MFG]  (hidden comment: GRM31CR70J226ME19K)
J23  TSW-102-08-G-S-RA  [TSW-102-08-G-S-RA]
L2  DFE201612PD-R15M=P2  [FP-DFE201612PD-R15M=P2_0806 (2016)-MFG]  (value not drawn)
L3  Ind_H: 470nH  [FP-DFE201210U-R47M=P2_0805 (2012)-MFG]  (hidden comment: DFE201210U-R47M=P2)
L5  Ind_H: 470nH  [FP-DFE201210U-R47M=P2_0805 (2012)-MFG]  (hidden comment: DFE201210U-R47M=P2)
L6  DFE201612PD-R15M=P2  [FP-DFE201612PD-R15M=P2_0806 (2016)-MFG]  (value not drawn)
R13  ValueDisplayed: 100k  [0402]  (hidden comment: CRCW0402100KFKED)
R16  value 0  [FP-ERJ-2GE0R00X_0402-MFG]  (hidden comment: ERJ-2GE0R00X)
R17  value 0  [FP-ERJ-2GE0R00X_0402-MFG]  (hidden comment: ERJ-2GE0R00X)
R18  WSL080500000ZEA9  [FP-WSL080500000ZEA9_0805-MFG]  (value not drawn)
R70  ValueDisplayed: 18.0k  [0402L]  (hidden comment: CRCW040218K0FKED)
R74  value 0  [FP-ERJ-2GE0R00X_0402-MFG]  (hidden comment: ERJ-2GE0R00X)
R75  Res_ohm: 100k  [FP-CRCW0402100KFKEDC_0402-IPC_B]  (hidden comment: CRCW0402100KFKEDC)
R76  ValueDisplayed: 18.0k  [0402L]  (hidden comment: CRCW040218K0FKED)
R79  Res_ohm: 100k  [FP-CRCW0402100KFKEDC_0402-IPC_B]  (hidden comment: CRCW0402100KFKEDC)
R84  ValueDisplayed: 3.32k  [0402]  (hidden comment: CRCW04023K32FKED)
R145  ValueDisplayed: 0  [0603]  (hidden comment: MCT06030Z0000ZP500)
R199  ValueDisplayed: 3.32k  [0402]  (hidden comment: CRCW04023K32FKED)
R200  Res_ohm: 100k  [FP-CRCW0402100KFKEDC_0402-IPC_B]  (hidden comment: CRCW0402100KFKEDC)
R201  ValueDisplayed: 100k  [0402]  (hidden comment: CRCW0402100KFKED)
R202  ValueDisplayed: 10.0k  [0402L]  (hidden comment: CRCW040210K0FKED)
R213  ValueDisplayed: 100k  [0402]  (hidden comment: CRCW0402100KFKED)
R214  ValueDisplayed: 10.0k  [0402L]  (hidden comment: CRCW040210K0FKED)
R217  value 0  [FP-ERJ-2GE0R00X_0402-MFG]  (hidden comment: ERJ-2GE0R00X)
TP7  TESTPOINT  [TP_VIA_060RND040]  (value not drawn)  (no BOM)
TP8  TESTPOINT  [TP_25MIL-SMT]  (value not drawn)  (no BOM)
U4  TPS78417QDBVRQ1  [DBV0005A-MFG]
U13  TPS6285020MQDRLRQ1  [DRL0008A-MFG]
U15  TPS6285021HQDRLRQ1  [DRL0008A-MFG]
U24  TLV75533PDRVR  [DRV0006A]

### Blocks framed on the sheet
LDO - 3.3V: C92 C93 R213 R214 R217 TP8 U24
VPP 1.7V LDO: C4 C7 J23 R13 R16 R17 U4

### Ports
NRESET (out), PGOOD

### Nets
5V_IN_USB: R214.2
GND: C4.1 C7.2 C32.1 C33.1 C35.2 C36.2 C42.2 C44.2 C45.2 C50.2 C51.2 C52.2 C53.2 C54.2 C55.1 C56.1 C88.1 C92.2 C93.1 C94.1 R13.1 R70.1 R76.1 R84.1 R199.1 R201.1 R213.1 TP7.1 U4.2(GND) U13.8(GND) U15.8(GND) U24.3(GND) U24.7(PAD)
REG_1V8: C32.2 L2.2 R18.1
REG_3V3: C56.2 L6.2 R75.2
REG_OUT_1V8: C33.2 C35.1 C36.1 C88.2 L2.1 L3.2 U13.5(FB)
REG_OUT_3V3: C51.1 C53.1 C55.2 C94.2 L5.2 L6.1 U15.5(FB)
VCC_1V8: R18.2
VCC_3V3: C92.1 R145.1 R202.2 TP8.1 U24.1(OUT)
VCC_5V: C42.1 C44.1 C45.1 C50.1 C52.1 C54.1 C93.2 J23.2 R79.1 R200.1 R217.2 U13.1(VIN) U13.2(EN) U15.1(VIN) U15.2(EN) U24.6(IN)
VCC_XDS_3V3: R145.2
VPP_1P7: C4.2 U4.5(OUT)
VPP_LDO_IN_5V: C7.1 J23.1 R17.2 U4.1(IN)
3V3_LDO_EN: R213.2 R214.1 R217.1 U24.4(EN)
COMP1: R76.2 U15.4(COMP/FSET)
COMP3: R70.2 U13.4(COMP/FSET)
MODE_1V8: R79.2 R84.2 U13.3(MODE/SYNC)
MODE_3V3: R199.2 R200.2 U15.3(MODE)
NRESET: R74.2 ; port NRESET
PGOOD: R16.1 R201.2 R202.1 ; port PGOOD
REG_PG: R74.1 R75.1 U13.6(PG) U15.6(PG)
SW1: L5.1 U15.7(SW)
SW3: L3.1 U13.7(SW)
VPP_LDO_EN: R13.2 R16.2 R17.1 U4.3(EN)

Not connected (* = marked no-connect by the designer): U4 4(NC)*; U24 2(NC)* 5(NC)*

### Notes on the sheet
- DC DC REGULATOR - 3.3V

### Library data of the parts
C4 = CMP-0094968-1: Multi-Layer Ceramic Capacitor 2.2uF 10V X7S ±10% 0402 Paper T/R; Manufacturer: Murata; AEC Grade: Grade 1; Cap_F: 2.2µF; SizeZ_mm: 0.7mm; Value: 2.2µF; AEC Qualified: Yes; TempCo: 22%
C7 = CMP-0006349-2: CAP, CERM, 1 uF, 10 V, +/- 10%, X7S, AEC-Q200 Grade 1, 0402; Manufacturer: MuRata; Polarized: N; Value: 1uF; U/M: EA; Cap_F: 1µF; Value1: Unknown; VDC_V: 10V; TaMin_C: -55°C; TaMax_C: 125°C; Cap_Case: 0402; SizeArea_mm2: 0.5; SizeAreaWB_mm2: 3; SizeX_mm: 1; SizeZ_mm: 0.7; AEC Category: Q200; AEC Qualified: Y
C32 = CMP-0008940-2: CAP, CERM, 47 uF, 6.3 V, +/- 20%, X5R, 1206; Manufacturer: MuRata; TaMin_C: -55°C; ESR_ohm: 3m; Polarized: N; SizeAreaWB_mm2: 10.92; Value1: 0.003 ohm; U/M: EA; Value: 47uF; TaMax_C: 85°C; SizeZ_mm: 1.8; SizeX_mm: 3.2; SizeY_mm: 1.6; Cap_Case: 1206; Value2: 6.3V; SizeArea_mm2: 5.12; Cap_F: 47µF; AEC Category: Q200
C33 C55 C56 C88 C94 = CMP-0092150-1: Chip Multilayer Ceramic Capacitors for General Purpose, 1206, 22uF, X7R, 15%, 20%, 6.3V; Manufacturer: Murata; SizeZ_mm: 1.8mm; AEC Qualified: No; Value: 22µF
C35 C36 C51 C53 = CMP-0007497-5: as C5 on sheet PROC212A_BP_MMWAVE_MODULE
C42 C54 = CMP-0007497-5: CAP, CERM, 10 uF, 10 V, +/- 20%, X7R, 0603; Manufacturer: MuRata; TaMin_C: -55°C; Polarized: N; SizeAreaWB_mm2: 4.68; Value1: Unknown; U/M: EA; Value: 10uF; TaMax_C: 125°C; SizeZ_mm: 1; SizeX_mm: 1.6; SizeY_mm: 0.8; Cap_Case: 0603; SizeArea_mm2: 1.28; AEC Category: Q200
C44 C52 = CMP-0007398-4: CAP, CERM, 0.47 uF, 16 V, +/- 10%, X7R, 0603; Manufacturer: MuRata; TaMin_C: -55°C; Polarized: N; SizeAreaWB_mm2: 4.68; Value1: Unknown; U/M: EA; Value: 0.47uF; TaMax_C: 125°C; SizeZ_mm: 1; SizeX_mm: 1.6; SizeY_mm: 0.8; Cap_Case: 0603; Value2: 16V; SizeArea_mm2: 1.28; AEC Category: Q200
C45 C50 = CMP-0006470-2: CAP, CERM, 470 pF, 50 V, +/- 5%, C0G/NP0, 0402; Manufacturer: MuRata; TaMin_C: -55°C; Polarized: N; SizeAreaWB_mm2: 3; Value1: Unknown; U/M: EA; Value: 470pF; TaMax_C: 125°C; SizeZ_mm: 0.6; SizeX_mm: 1; SizeY_mm: 0.5; Cap_Case: 0402; Value2: 50V; AEC Category: Q200
C92 C93 = CMP-0094968-1: Multi-Layer Ceramic Capacitor 2.2uF 10V X7S ±10% 0402 Paper T/R; Manufacturer: Murata; TempCo: 22%; Value: 2.2µF; SizeZ_mm: 0.7mm; AEC Qualified: Yes; AEC Grade: Grade 1
J23 = CMP-0055976-1: as J12 on sheet PROC212A_BP_MMWAVE_MODULE
L2 L6 = CMP-0126126-1: Shielded Wirewound Inductor 0.15uH 20% 5200mA 0.018Ω 0806 (2016); Manufacturer: Murata; AEC Qualified: No; DCR_ohm: 18m; Ind_H: 150nH; Isat: 6200mA; Material: Metal Alloy; SizeZ_mm: 1.2mm; Shrouded: true; Test Frequency: 1MHz; Tolerance_%: 0.2%
L3 L5 = CMP-0092096-1: 470nH Shielded Wirewound Inductor 3A 42mOhm Max 0805 (2012 Metric); Manufacturer: Murata; DCR_ohm: 0.042; Shrouded: true; SizeZ_mm: 1mm; Value: 0.47uH; Tolerance_%: 20%; Test Frequency: 1MHz; Isat: 4.4A; AEC Qualified: No; Material: Metal Alloy
R13 R201 R213 = CMP-0025950-3: RES, 100 k, 1%, 0.063 W, AEC-Q200 Grade 0, 0402; Manufacturer: Vishay-Dale; Power_W: 63mW; TempCo: 100 ppm/C; Value: 100k; EIA_Code: E96; SizeX_mm: 1; SizeY_mm: 0.5; SizeZ_mm: 0.6; Value2: 0.063W; AEC Qualified: Y; VDC_V: 50V; AEC Category: Q200; AEC Grade: 0
R16 R17 R74 R217 = CMP-0002710-1: 0 Ohms Jumper Chip Resistor 0402 (1005 Metric) Automotive AEC-Q200 Thick Film; Manufacturer: Panasonic; SizeZ_mm: 0.4mm; AEC Qualified: Yes; AEC Grade: Grade 0; Power: 100mW
R18 = CMP-0122265-1: 0 Ohms Jumper Chip Resistor 0805 (2012 Metric) Metal Element; Manufacturer: Vishay; AEC Qualified: No; Power_W: 125mW; Res_ohm: 0; SizeZ_mm: 0.457mm; TempCo: 3900ppm/°C; Value: 0
R70 R76 = CMP-0026058-3: RES, 18.0 k, 1%, 0.063 W, AEC-Q200 Grade 0, 0402; Manufacturer: Vishay-Dale; Power_W: 63mW; TempCo: 100 ppm/C; Value_Code: 18k0; Value: 18.0k; Res_ohm: 18k; SizeX_mm: 1; SizeY_mm: 0.5; SizeZ_mm: 0.6; Value2: 0.063W; AEC Qualified: Y; VDC_V: 50V; AEC Grade: 0; AEC Category: Q200
R75 R79 R200 = CMP-0092204-1: as R72 on sheet PROC212A_USB_DC_JACK_PWR_Switch
R84 R199 = CMP-0026333-2: RES, 3.32 k, 1%, 0.063 W, AEC-Q200 Grade 0, 0402; Manufacturer: Vishay-Dale; Power_W: 63mW; TempCo: 100 ppm/C; Value_Code: 3k32; Value: 3.32k; EIA_Code: E96; SizeX_mm: 1; SizeY_mm: 0.5; SizeZ_mm: 0.6; Value2: 0.063W; AEC Qualified: Y; VDC_V: 50V; AEC Category: Q200; AEC Grade: 0
R145 = CMP-0025884-3: RES, 0, 5%, 0.125 W, 0603; Manufacturer: Vishay/Beyschlag; Power_W: 125mW; TempCo: ppm/C; Value_Code: 0000; U/M: EA; Value: 0; EIA_Code: E24; SizeX_mm: 1.6; SizeY_mm: 0.8; SizeZ_mm: 1; Value2: 0.125W; SizeArea_mm2: 1.28; CompType: Resistor; AEC Qualified: N; AEC Category: Q200; INSTALATION: DNP
R202 R214 = CMP-0025958-3: as R63 on sheet PROC212A_USB_DC_JACK_PWR_Switch
TP7 TP8 = CMP-0078143-3: TEST POINT.  No entry in BOM.
U4 = CMP-0092338-1: Linear Voltage Regulator IC Positive Fixed Output 300mA SOT-23-5; Manufacturer: Texas Instruments; TaMin_C: -40°C; Output Voltage: 1.7V; Standoff Height: 0mm; SizeZ_mm: 1.45mm; TaMax_C: +125°C; Accuracy Percentage: 0.5%; AEC Grade: Grade 1; Number Of Outputs: 1; AEC Qualified: Yes; Max Supply Voltage: 6V; Dropout Voltage: 900mV; Nominal Supply Current: 0.033mA; Min Supply Voltage: 1.65V; TJmax_C: +150°C
U13 = CMP-0088311-1: 2.7-V to 6-V Adjustable-Frequency Step-Down Converter in SOT583 Package; Manufacturer: Texas Instruments; Number Of Outputs: 1; Max Supply Voltage: 6V; Max Duty Cycle: 100%; Min Supply Voltage: 2.7V; Switching Frequency: 1.8-3.5MHz; Nominal Supply Current: 15uA; SizeZ_mm: 0.6mm; Switching Topology: Buck; AEC Grade: Grade 1; TJmax_C: +150°C; TaMin_C: -40°C; Standoff Height: 0mm; Output Type: Fixed; Output Voltage: 1.8V; AEC Qualified: Yes; TaMax_C: +125°C
U15 = CMP-0092337-2: 2.7-V to 6-V, 2-A Automotive Step-Down Converter in SOT583 Package; Manufacturer: Texas Instruments; TaMax_C: +125°C; Switching Topology: Buck; Max Duty Cycle: 100%; Min Supply Voltage: 2.7V; TJmax_C: +150°C; Number Of Outputs: 1; Switching Frequency: 1.8-4MHz; TaMin_C: -40°C; Max Supply Voltage: 6V; SizeZ_mm: 0.6mm; Nominal Supply Current: 17uA; Standoff Height: 0mm; AEC Qualified: Yes; Output Voltage: 0.6-5.5V; Output Type: AdjustableProgrammable; AEC Grade: Grade 1; AEC Category: Q200; CompType: IC
U24 = CMP-0013427-7: 500mA LDO, DRV0006A (WSON-6); Manufacturer: Texas Instruments; SizeX_mm: 2; CompType: IC; SizeZ_mm: 0.8; SizeArea_mm2: 4; SizeAreaWB_mm2: 9; U/M: EA

## Sheet PROC212A_ANALOG_MUX_LVDS_DRIVER.SchDoc: ANALOG_MUX_LVDS_DRIVER
size 431 x 279 mm; Date: Not shown in title block; ApprovedBy: Not shown in title block; CheckedBy: Not shown in title block; Author: Not shown in title block; CompanyName: Not shown in title block; DrawnBy: Mistral; Engineer: Not shown in title block; Organization: Not shown in title block; Address1: Not shown in title block; Address2: Not shown in title block; Address3: Not shown in title block; Address4: Not shown in title block; DocumentNumber: 7; Revision: Use project parameter SCH_Rev; SheetNumber: 7; SheetTotal: 15; PageSetup: Record=PageOptions¦CenterHorizontal=True¦CenterVertical=True¦PrintScale=1.00¦XCorrection=1.00¦YCorrection=1.00¦PrintKind=0¦BorderSize=5000000¦LeftOffset=0¦BottomOffset=0¦Orientation=2¦PaperLength=1000¦PaperWidth=1000¦Scale=100¦PaperSource=15¦PrintQuality=600¦MediaType=1¦DitherType=10¦PaperKind=Letter¦PrintScaleMode=1
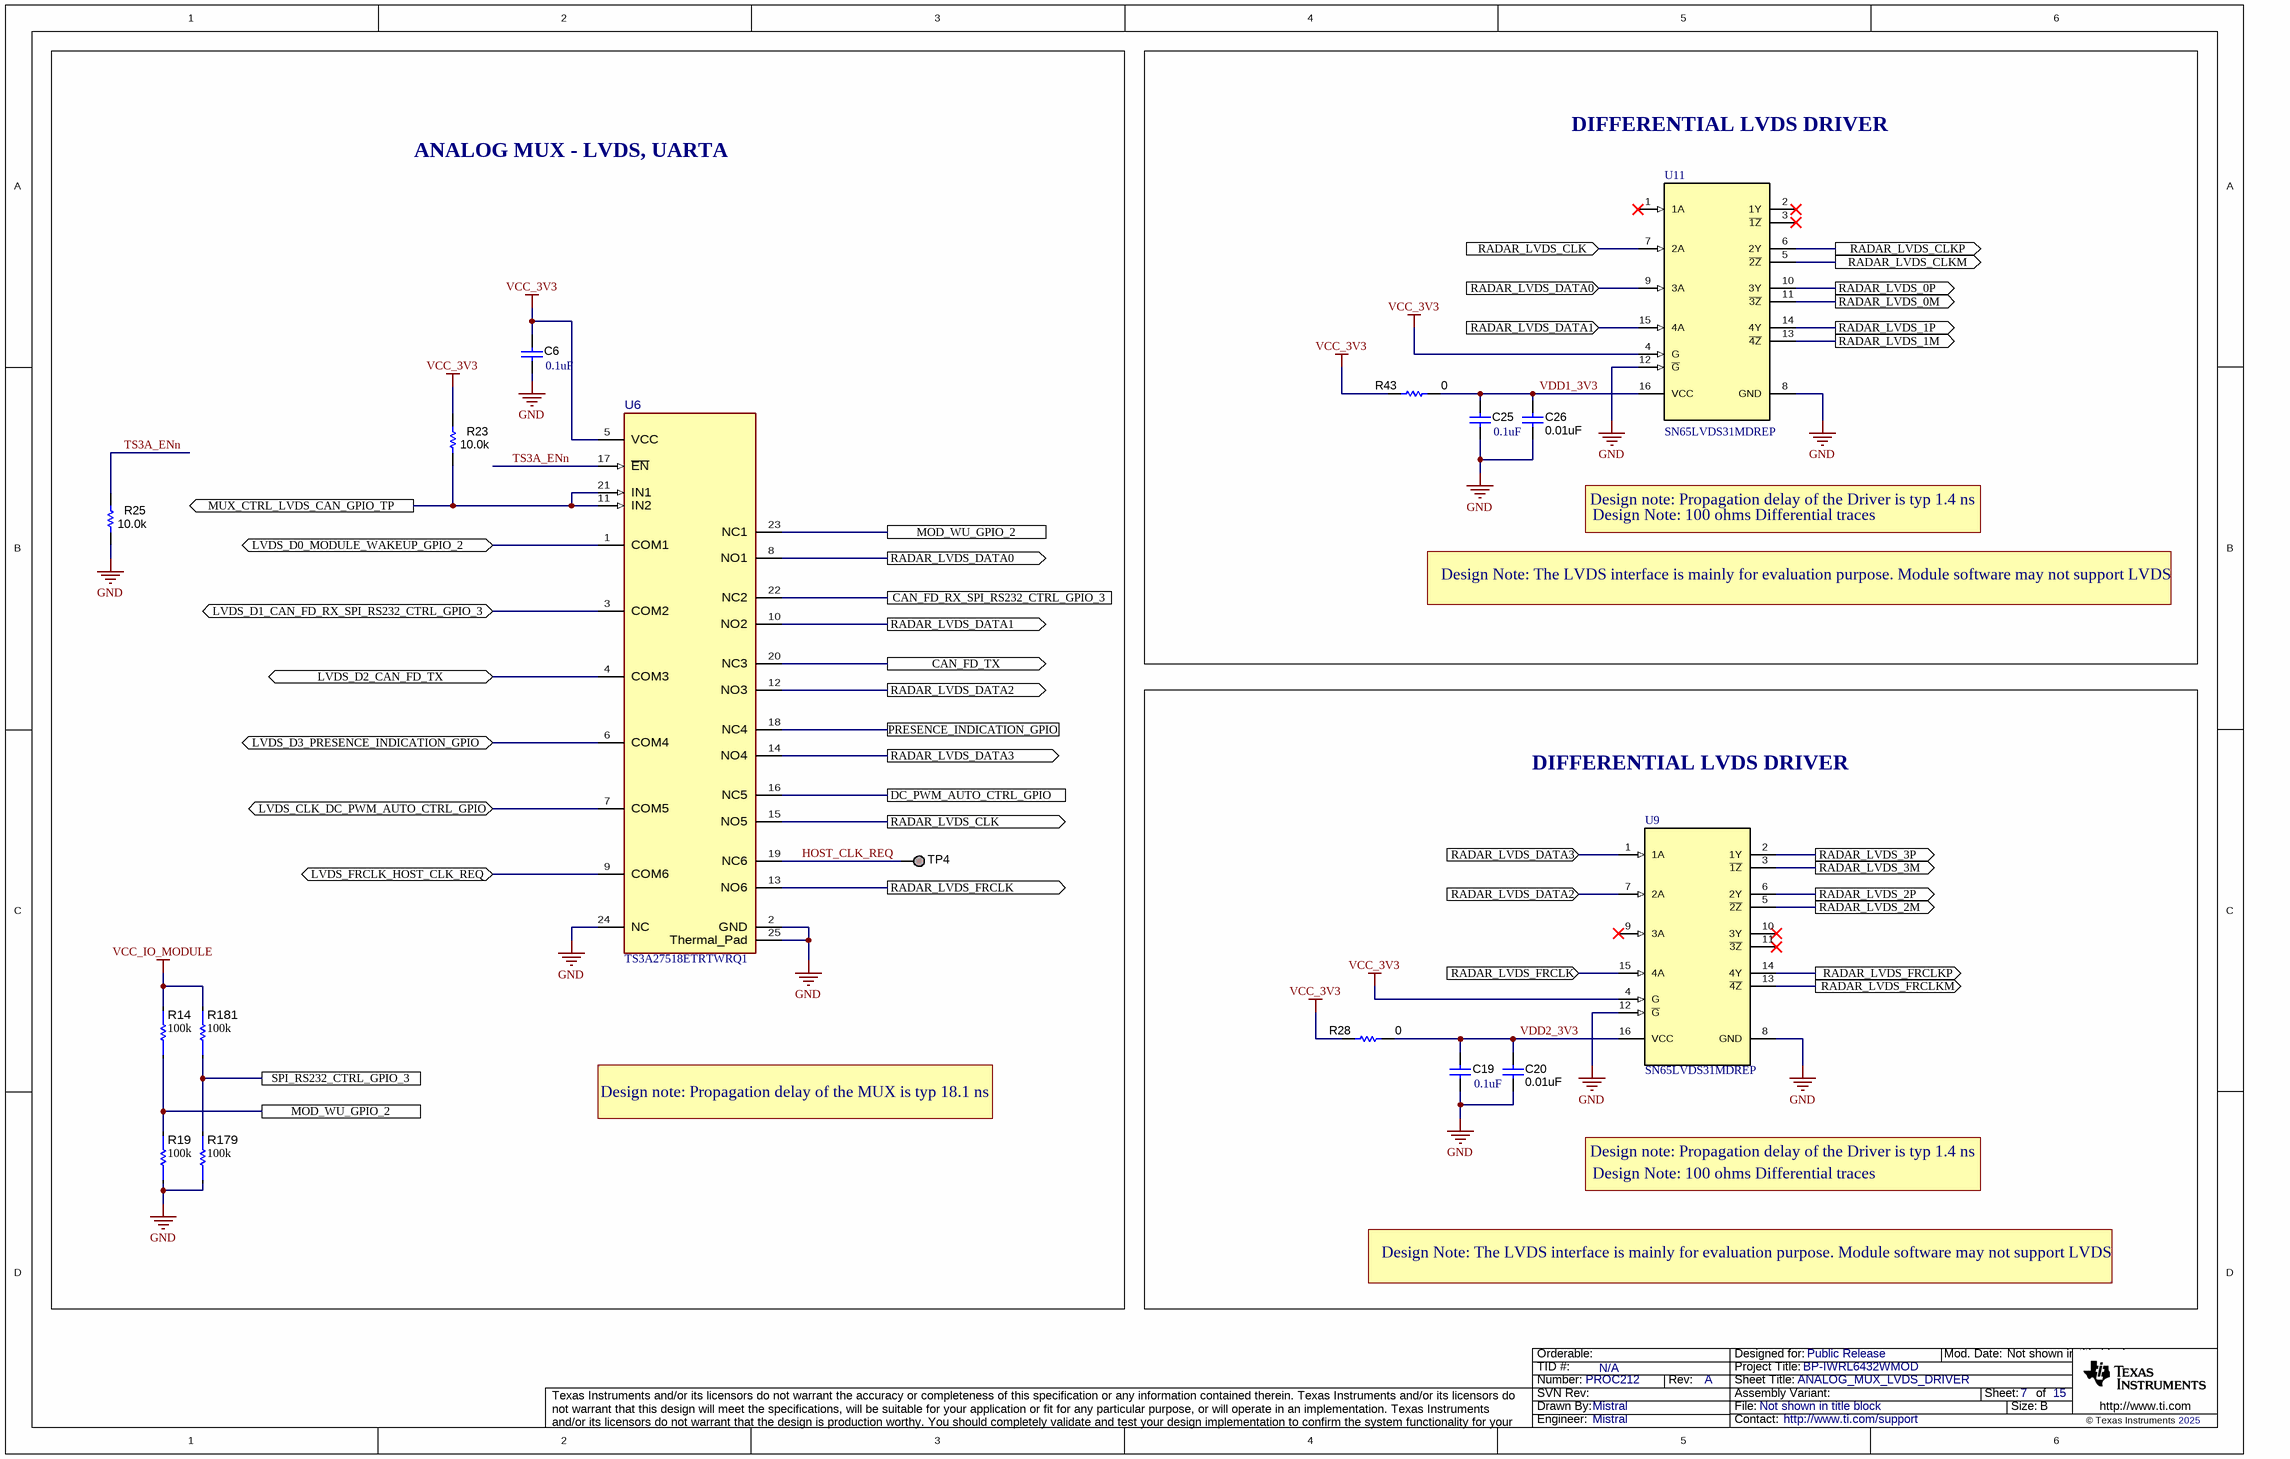
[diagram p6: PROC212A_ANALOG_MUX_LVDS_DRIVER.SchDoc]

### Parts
C6  ValueDisplayed: 0.1uF  [0402]  (hidden comment: GCM155R71H104KE02D)
C19  ValueDisplayed: 0.1uF  [0402]  (hidden comment: GCM155R71H104KE02D)
C20  ValueDisplayed: 0.01uF  [0402L]  (hidden comment: GCM155R71E103KA37D)
C25  ValueDisplayed: 0.1uF  [0402]  (hidden comment: GCM155R71H104KE02D)
C26  ValueDisplayed: 0.01uF  [0402L]  (hidden comment: GCM155R71E103KA37D)
R14  Res_ohm: 100k  [FP-CRCW0402100KFKEDC_0402-IPC_B]  (hidden comment: CRCW0402100KFKEDC)
R19  Res_ohm: 100k  [FP-CRCW0402100KFKEDC_0402-IPC_B]  (hidden comment: CRCW0402100KFKEDC)
R23  ValueDisplayed: 10.0k  [0402L]  (hidden comment: CRCW040210K0FKED)
R25  ValueDisplayed: 10.0k  [0402L]  (hidden comment: CRCW040210K0FKED)
R28  ValueDisplayed: 0  [0603]  (hidden comment: MCT06030Z0000ZP500)
R43  ValueDisplayed: 0  [0603]  (hidden comment: MCT06030Z0000ZP500)
R179  Res_ohm: 100k  [FP-CRCW0402100KFKEDC_0402-IPC_B]  (hidden comment: CRCW0402100KFKEDC)
R181  Res_ohm: 100k  [FP-CRCW0402100KFKEDC_0402-IPC_B]  (hidden comment: CRCW0402100KFKEDC)
TP4  TESTPOINT  [TP_25MIL-SMT]  (value not drawn)  (no BOM)
U6  TS3A27518ETRTWRQ1  [RTW0024B-MFG]
U9  SN65LVDS31MDREP  [D0016A_N]
U11  SN65LVDS31MDREP  [D0016A_N]

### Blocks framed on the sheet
ANALOG MUX - LVDS, UARTA: C6 R14 R19 R23 R25 R179 R181 TP4 U6
DIFFERENTIAL LVDS DRIVER: C25 C26 R43 U11
DIFFERENTIAL LVDS DRIVER: C19 C20 R28 U9

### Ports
CAN_FD_RX_SPI_RS232_CTRL_GPIO_3, CAN_FD_TX (out), DC_PWM_AUTO_CTRL_GPIO, LVDS_CLK_DC_PWM_AUTO_CTRL_GPIO (bidir), LVDS_D0_MODULE_WAKEUP_GPIO_2 (bidir), LVDS_D1_CAN_FD_RX_SPI_RS232_CTRL_GPIO_3 (bidir), LVDS_D2_CAN_FD_TX (bidir), LVDS_D3_PRESENCE_INDICATION_GPIO (bidir), LVDS_FRCLK_HOST_CLK_REQ (bidir), MOD_WU_GPIO_2, MUX_CTRL_LVDS_CAN_GPIO_TP (out), PRESENCE_INDICATION_GPIO, RADAR_LVDS_0M (out), RADAR_LVDS_0P (out), RADAR_LVDS_1M (out), RADAR_LVDS_1P (out), RADAR_LVDS_2M (out), RADAR_LVDS_2P (out), RADAR_LVDS_3M (out), RADAR_LVDS_3P (out), RADAR_LVDS_CLK (in), RADAR_LVDS_CLK (out), RADAR_LVDS_CLKM (out), RADAR_LVDS_CLKP (out), RADAR_LVDS_DATA0 (in), RADAR_LVDS_DATA0 (out), RADAR_LVDS_DATA1 (in), RADAR_LVDS_DATA1 (out), RADAR_LVDS_DATA2 (in), RADAR_LVDS_DATA2 (out), RADAR_LVDS_DATA3 (in), RADAR_LVDS_DATA3 (out), RADAR_LVDS_FRCLK (in), RADAR_LVDS_FRCLK (out), RADAR_LVDS_FRCLKM (out), RADAR_LVDS_FRCLKP (out), SPI_RS232_CTRL_GPIO_3

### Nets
GND: C6.2 C19.2 C20.2 C25.2 C26.2 R19.1 R25.2 R179.1 U6.2(GND) U6.24(NC) U6.25(Thermal_Pad) U9.8(GND) U9.12(~{G}) U11.8(GND) U11.12(~{G})
VCC_3V3: C6.1 R23.1 R28.1 R43.1 U6.5(VCC) U9.4(G) U11.4(G)
VCC_IO_MODULE: R14.2 R181.2
CAN_FD_RX_SPI_RS232_CTRL_GPIO_3: U6.22(NC2) ; port CAN_FD_RX_SPI_RS232_CTRL_GPIO_3
CAN_FD_TX: U6.20(NC3) ; port CAN_FD_TX
DC_PWM_AUTO_CTRL_GPIO: U6.16(NC5) ; port DC_PWM_AUTO_CTRL_GPIO
HOST_CLK_REQ: TP4.1 U6.19(NC6)
LVDS_CLK_DC_PWM_AUTO_CTRL_GPIO: U6.7(COM5) ; port LVDS_CLK_DC_PWM_AUTO_CTRL_GPIO
LVDS_D0_MODULE_WAKEUP_GPIO_2: U6.1(COM1) ; port LVDS_D0_MODULE_WAKEUP_GPIO_2
LVDS_D1_CAN_FD_RX_SPI_RS232_CTRL_GPIO_3: U6.3(COM2) ; port LVDS_D1_CAN_FD_RX_SPI_RS232_CTRL_GPIO_3
LVDS_D2_CAN_FD_TX: U6.4(COM3) ; port LVDS_D2_CAN_FD_TX
LVDS_D3_PRESENCE_INDICATION_GPIO: U6.6(COM4) ; port LVDS_D3_PRESENCE_INDICATION_GPIO
LVDS_FRCLK_HOST_CLK_REQ: U6.9(COM6) ; port LVDS_FRCLK_HOST_CLK_REQ
MOD_WU_GPIO_2: R14.1 R19.2 U6.23(NC1) ; port MOD_WU_GPIO_2
MUX_CTRL_LVDS_CAN_GPIO_TP: R23.2 U6.11(IN2) U6.21(IN1) ; port MUX_CTRL_LVDS_CAN_GPIO_TP
PRESENCE_INDICATION_GPIO: U6.18(NC4) ; port PRESENCE_INDICATION_GPIO
RADAR_LVDS_0M: U11.11(~{3Z}) ; port RADAR_LVDS_0M
RADAR_LVDS_0P: U11.10(3Y) ; port RADAR_LVDS_0P
RADAR_LVDS_1M: U11.13(~{4Z}) ; port RADAR_LVDS_1M
RADAR_LVDS_1P: U11.14(4Y) ; port RADAR_LVDS_1P
RADAR_LVDS_2M: U9.5(~{2Z}) ; port RADAR_LVDS_2M
RADAR_LVDS_2P: U9.6(2Y) ; port RADAR_LVDS_2P
RADAR_LVDS_3M: U9.3(~{1Z}) ; port RADAR_LVDS_3M
RADAR_LVDS_3P: U9.2(1Y) ; port RADAR_LVDS_3P
RADAR_LVDS_CLK: U6.15(NO5) U11.7(2A) ; port RADAR_LVDS_CLK
RADAR_LVDS_CLKM: U11.5(~{2Z}) ; port RADAR_LVDS_CLKM
RADAR_LVDS_CLKP: U11.6(2Y) ; port RADAR_LVDS_CLKP
RADAR_LVDS_DATA0: U6.8(NO1) U11.9(3A) ; port RADAR_LVDS_DATA0
RADAR_LVDS_DATA1: U6.10(NO2) U11.15(4A) ; port RADAR_LVDS_DATA1
RADAR_LVDS_DATA2: U6.12(NO3) U9.7(2A) ; port RADAR_LVDS_DATA2
RADAR_LVDS_DATA3: U6.14(NO4) U9.1(1A) ; port RADAR_LVDS_DATA3
RADAR_LVDS_FRCLK: U6.13(NO6) U9.15(4A) ; port RADAR_LVDS_FRCLK
RADAR_LVDS_FRCLKM: U9.13(~{4Z}) ; port RADAR_LVDS_FRCLKM
RADAR_LVDS_FRCLKP: U9.14(4Y) ; port RADAR_LVDS_FRCLKP
SPI_RS232_CTRL_GPIO_3: R179.2 R181.1 ; port SPI_RS232_CTRL_GPIO_3
TS3A_ENn: R25.1 U6.17(~{EN})
VDD1_3V3: C25.1 C26.1 R43.2 U11.16(VCC)
VDD2_3V3: C19.1 C20.1 R28.2 U9.16(VCC)

Not connected (* = marked no-connect by the designer): U9 9(3A)* 10(3Y)* 11(~{3Z})*; U11 1(1A)* 2(1Y)* 3(~{1Z})*

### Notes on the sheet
- Design Note: 100 ohms Differential traces
- Design note: Propagation delay of the Driver is typ 1.4 ns
- Design Note: The LVDS interface is mainly for evaluation purpose. Module software may not support LVDS
- Design note: Propagation delay of the MUX is typ 18.1 ns

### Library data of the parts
C6 C19 C25 = CMP-0006356-2: as C39 on sheet PROC212A_USB_DC_JACK_PWR_Switch
C20 C26 = CMP-0006352-2: CAP, CERM, 0.01 uF, 25 V, +/- 10%, X7R, 0402; Manufacturer: MuRata; TaMin_C: -55°C; Polarized: N; SizeAreaWB_mm2: 3; Value1: Unknown; U/M: EA; Value: 0.01uF; TaMax_C: 125°C; SizeZ_mm: 0.6; SizeX_mm: 1; SizeY_mm: 0.5; Cap_Case: 0402; Value2: 25V; CompType: Capacitor; Cap_F: 10nF; AEC Category: Q200
R14 R19 R179 R181 = CMP-0092204-1: as R72 on sheet PROC212A_USB_DC_JACK_PWR_Switch
R23 R25 = CMP-0025958-3: as R63 on sheet PROC212A_USB_DC_JACK_PWR_Switch
R28 R43 = CMP-0025884-3: as R145 on sheet PROC212A_DC_Regulators
TP4 = CMP-0078143-3: TEST POINT.  No entry in BOM.
U6 = CMP-0125538-1: Automotive 3.3-V, 2:1 (SPDT), 6-channel, analog multiplexer with 1.8-V compatible control inputs; Manufacturer: Texas Instruments; SizeZ_mm: 0.8mm; AEC Qualified: Yes; -3Db Bandwith: 240MHz; AEC Grade: Grade 2; Max Supply Voltage: 3.6V; Min Supply Voltage: 1.65V; Nominal Supply Current: 0.01-0.04uA; On State Resistance: 4.4Ω; PositionCount: 6; Standoff Height: 0mm; TaMax_C: +105°C; TaMin_C: -40°C
U9 U11 = CMP-0029468-1: 400 Mbps Enhanced Product Quad LVDS Transmitter with LVTTL Input and Output, 4 Tx and 0 Rx, -55 to +125 degC, 16-pin SOIC (D), Green (RoHS & no Sb/Br); Manufacturer: Texas Instruments; ESD HBM(kV): 8; Signaling Rate(Mbps): 400; ICC(Max)(mA): 35; No. of Tx: 4; SubFamily: LVDS PHY (<800Mbps)

## Sheet PROC212A_ANALOG_MUX_SPI.SchDoc: ANALOG_MUX_SPI
size 431 x 279 mm; Date: Not shown in title block; ApprovedBy: Not shown in title block; CheckedBy: Not shown in title block; Author: Not shown in title block; CompanyName: Not shown in title block; DrawnBy: Mistral; Engineer: Mistral; Organization: Not shown in title block; Address1: Not shown in title block; Address2: Not shown in title block; Address3: Not shown in title block; Address4: Not shown in title block; DocumentNumber: 8; Revision: Use project parameter SCH_Rev; SheetNumber: 8; SheetTotal: 15; PageSetup: Record=PageOptions¦CenterHorizontal=True¦CenterVertical=True¦PrintScale=1.00¦XCorrection=1.00¦YCorrection=1.00¦PrintKind=0¦BorderSize=5000000¦LeftOffset=0¦BottomOffset=0¦Orientation=2¦PaperLength=1000¦PaperWidth=1000¦Scale=100¦PaperSource=15¦PrintQuality=600¦MediaType=1¦DitherType=10¦PaperKind=Letter¦PrintScaleMode=1
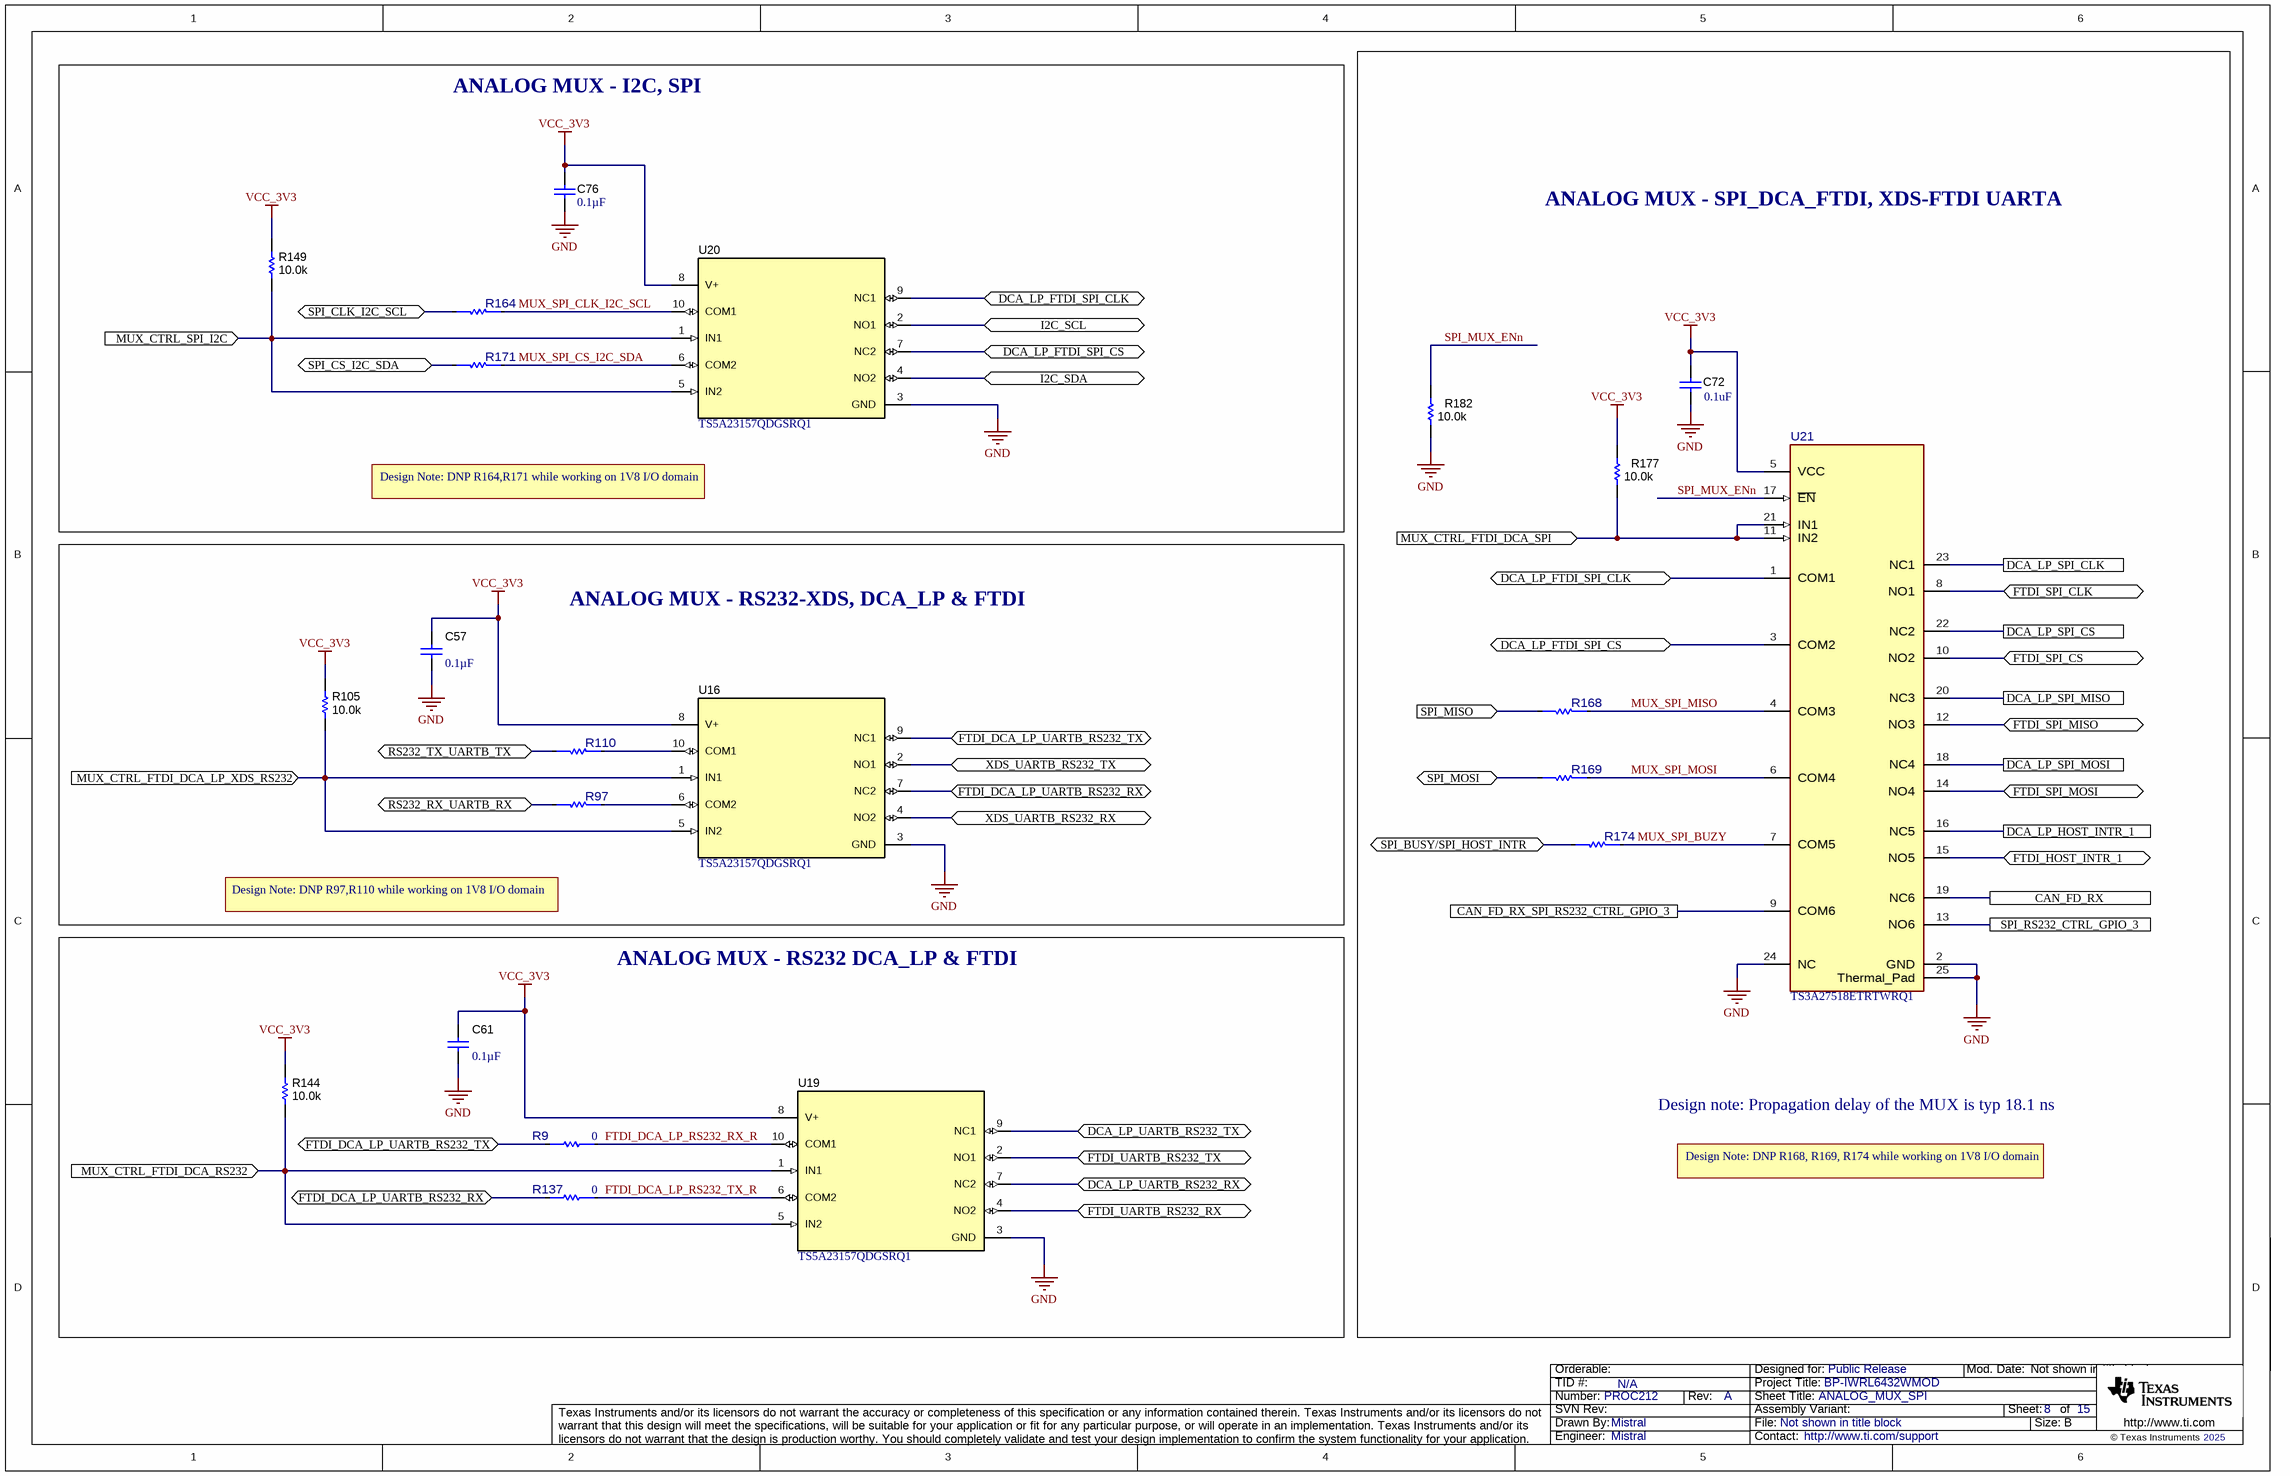
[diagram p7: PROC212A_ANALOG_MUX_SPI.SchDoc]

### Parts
C57  ValueDisplayed: 0.1µF  [0402]  (hidden comment: C0402C104K8RACTU)
C61  ValueDisplayed: 0.1µF  [0402]  (hidden comment: C0402C104K8RACTU)
C72  ValueDisplayed: 0.1uF  [0402]  (hidden comment: GCM155R71H104KE02D)
C76  ValueDisplayed: 0.1µF  [0402]  (hidden comment: C0402C104K8RACTU)
R9  value 0  [FP-ERJ-2GE0R00X_0402-MFG]  (hidden comment: ERJ-2GE0R00X)
R97  ERJ-2GE0R00X  [FP-ERJ-2GE0R00X_0402-MFG]  (value not drawn)
R105  ValueDisplayed: 10.0k  [0402L]  (hidden comment: CRCW040210K0FKED)
R110  ERJ-2GE0R00X  [FP-ERJ-2GE0R00X_0402-MFG]  (value not drawn)
R137  value 0  [FP-ERJ-2GE0R00X_0402-MFG]  (hidden comment: ERJ-2GE0R00X)
R144  ValueDisplayed: 10.0k  [0402L]  (hidden comment: CRCW040210K0FKED)
R149  ValueDisplayed: 10.0k  [0402L]  (hidden comment: CRCW040210K0FKED)
R164  ERJ-2GE0R00X  [FP-ERJ-2GE0R00X_0402-MFG]  (value not drawn)
R168  ERJ-2GE0R00X  [FP-ERJ-2GE0R00X_0402-MFG]  (value not drawn)
R169  ERJ-2GE0R00X  [FP-ERJ-2GE0R00X_0402-MFG]  (value not drawn)
R171  ERJ-2GE0R00X  [FP-ERJ-2GE0R00X_0402-MFG]  (value not drawn)
R174  ERJ-2GE0R00X  [FP-ERJ-2GE0R00X_0402-MFG]  (value not drawn)
R177  ValueDisplayed: 10.0k  [0402L]  (hidden comment: CRCW040210K0FKED)
R182  ValueDisplayed: 10.0k  [0402L]  (hidden comment: CRCW040210K0FKED)
U16  TS5A23157QDGSRQ1  [DGS0010A_N]
U19  TS5A23157QDGSRQ1  [DGS0010A_N]
U20  TS5A23157QDGSRQ1  [DGS0010A_N]
U21  TS3A27518ETRTWRQ1  [RTW0024B-MFG]

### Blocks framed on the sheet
ANALOG MUX - SPI_DCA_FTDI, XDS-FTDI UARTA: C72 R168 R169 R174 R177 R182 U21
ANALOG MUX - I2C, SPI: C76 R149 R164 R171 U20
ANALOG MUX - RS232-XDS, DCA_LP & FTDI: C57 R97 R105 R110 U16
ANALOG MUX - RS232 DCA_LP & FTDI: C61 R9 R137 R144 U19

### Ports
CAN_FD_RX, CAN_FD_RX_SPI_RS232_CTRL_GPIO_3, DCA_LP_FTDI_SPI_CLK (bidir), DCA_LP_FTDI_SPI_CS (bidir), DCA_LP_HOST_INTR_1, DCA_LP_SPI_CLK, DCA_LP_SPI_CS, DCA_LP_SPI_MISO, DCA_LP_SPI_MOSI, DCA_LP_UARTB_RS232_RX (bidir), DCA_LP_UARTB_RS232_TX (bidir), FTDI_DCA_LP_UARTB_RS232_RX (bidir), FTDI_DCA_LP_UARTB_RS232_TX (bidir), FTDI_HOST_INTR_1 (bidir), FTDI_SPI_CLK (bidir), FTDI_SPI_CS (bidir), FTDI_SPI_MISO (bidir), FTDI_SPI_MOSI (bidir), FTDI_UARTB_RS232_RX (bidir), FTDI_UARTB_RS232_TX (bidir), I2C_SCL (bidir), I2C_SDA (bidir), MUX_CTRL_FTDI_DCA_LP_XDS_RS232 (in), MUX_CTRL_FTDI_DCA_RS232 (in), MUX_CTRL_FTDI_DCA_SPI (in), MUX_CTRL_SPI_I2C (in), RS232_RX_UARTB_RX (bidir), RS232_TX_UARTB_TX (bidir), SPI_BUSY/SPI_HOST_INTR (bidir), SPI_CLK_I2C_SCL (bidir), SPI_CS_I2C_SDA (bidir), SPI_MISO (in), SPI_MOSI (bidir), SPI_RS232_CTRL_GPIO_3, XDS_UARTB_RS232_RX (bidir), XDS_UARTB_RS232_TX (bidir)

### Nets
GND: C57.2 C61.2 C72.2 C76.2 R182.2 U16.3(GND) U19.3(GND) U20.3(GND) U21.2(GND) U21.24(NC) U21.25(Thermal_Pad)
VCC_3V3: C57.1 C61.1 C72.1 C76.1 R105.2 R144.2 R149.2 R177.1 U16.8(V+) U19.8(V+) U20.8(V+) U21.5(VCC)
CAN_FD_RX: U21.19(NC6) ; port CAN_FD_RX
CAN_FD_RX_SPI_RS232_CTRL_GPIO_3: U21.9(COM6) ; port CAN_FD_RX_SPI_RS232_CTRL_GPIO_3
DCA_LP_FTDI_SPI_CLK: U20.9(NC1) U21.1(COM1) ; port DCA_LP_FTDI_SPI_CLK
DCA_LP_FTDI_SPI_CS: U20.7(NC2) U21.3(COM2) ; port DCA_LP_FTDI_SPI_CS
DCA_LP_HOST_INTR_1: U21.16(NC5) ; port DCA_LP_HOST_INTR_1
DCA_LP_SPI_CLK: U21.23(NC1) ; port DCA_LP_SPI_CLK
DCA_LP_SPI_CS: U21.22(NC2) ; port DCA_LP_SPI_CS
DCA_LP_SPI_MISO: U21.20(NC3) ; port DCA_LP_SPI_MISO
DCA_LP_SPI_MOSI: U21.18(NC4) ; port DCA_LP_SPI_MOSI
DCA_LP_UARTB_RS232_RX: U19.7(NC2) ; port DCA_LP_UARTB_RS232_RX
DCA_LP_UARTB_RS232_TX: U19.9(NC1) ; port DCA_LP_UARTB_RS232_TX
FTDI_DCA_LP_RS232_RX_R: R9.1 U19.10(COM1)
FTDI_DCA_LP_RS232_TX_R: R137.1 U19.6(COM2)
FTDI_DCA_LP_UARTB_RS232_RX: R137.2 U16.7(NC2) ; port FTDI_DCA_LP_UARTB_RS232_RX
FTDI_DCA_LP_UARTB_RS232_TX: R9.2 U16.9(NC1) ; port FTDI_DCA_LP_UARTB_RS232_TX
FTDI_HOST_INTR_1: U21.15(NO5) ; port FTDI_HOST_INTR_1
FTDI_SPI_CLK: U21.8(NO1) ; port FTDI_SPI_CLK
FTDI_SPI_CS: U21.10(NO2) ; port FTDI_SPI_CS
FTDI_SPI_MISO: U21.12(NO3) ; port FTDI_SPI_MISO
FTDI_SPI_MOSI: U21.14(NO4) ; port FTDI_SPI_MOSI
FTDI_UARTB_RS232_RX: U19.4(NO2) ; port FTDI_UARTB_RS232_RX
FTDI_UARTB_RS232_TX: U19.2(NO1) ; port FTDI_UARTB_RS232_TX
I2C_SCL: U20.2(NO1) ; port I2C_SCL
I2C_SDA: U20.4(NO2) ; port I2C_SDA
MUX_CTRL_FTDI_DCA_LP_XDS_RS232: R105.1 U16.1(IN1) U16.5(IN2) ; port MUX_CTRL_FTDI_DCA_LP_XDS_RS232
MUX_CTRL_FTDI_DCA_RS232: R144.1 U19.1(IN1) U19.5(IN2) ; port MUX_CTRL_FTDI_DCA_RS232
MUX_CTRL_FTDI_DCA_SPI: R177.2 U21.11(IN2) U21.21(IN1) ; port MUX_CTRL_FTDI_DCA_SPI
MUX_CTRL_SPI_I2C: R149.1 U20.1(IN1) U20.5(IN2) ; port MUX_CTRL_SPI_I2C
MUX_SPI_BUZY: R174.1 U21.7(COM5)
MUX_SPI_CLK_I2C_SCL: R164.1 U20.10(COM1)
MUX_SPI_CS_I2C_SDA: R171.1 U20.6(COM2)
MUX_SPI_MISO: R168.1 U21.4(COM3)
MUX_SPI_MOSI: R169.1 U21.6(COM4)
RS232_RX_UARTB_RX: R97.2 ; port RS232_RX_UARTB_RX
RS232_TX_UARTB_TX: R110.2 ; port RS232_TX_UARTB_TX
SPI_BUSY/SPI_HOST_INTR: R174.2 ; port SPI_BUSY/SPI_HOST_INTR
SPI_CLK_I2C_SCL: R164.2 ; port SPI_CLK_I2C_SCL
SPI_CS_I2C_SDA: R171.2 ; port SPI_CS_I2C_SDA
SPI_MISO: R168.2 ; port SPI_MISO
SPI_MOSI: R169.2 ; port SPI_MOSI
SPI_MUX_ENn: R182.1 U21.17(~{EN})
SPI_RS232_CTRL_GPIO_3: U21.13(NO6) ; port SPI_RS232_CTRL_GPIO_3
XDS_UARTB_RS232_RX: U16.4(NO2) ; port XDS_UARTB_RS232_RX
XDS_UARTB_RS232_TX: U16.2(NO1) ; port XDS_UARTB_RS232_TX
NetR97_1: R97.1 U16.6(COM2)
NetR110_1: R110.1 U16.10(COM1)

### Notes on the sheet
- Design Note: DNP R164,R171 while working on 1V8 I/O domain
- Design Note: DNP R97,R110 while working on 1V8 I/O domain
- Design note: Propagation delay of the MUX is typ 18.1 ns
- Design Note: DNP R168, R169, R174 while working on 1V8 I/O domain

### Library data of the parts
C57 C61 C76 = CMP-0078241-1: CAP, CERM, 0.1 µF, 10 V,+/- 10%, X7R, 0402; Manufacturer: Kemet; TaMin_C: -55°C; Polarized: N; SizeAreaWB_mm2: 3; U/M: EA; Value: 0.1uF; TaMax_C: 125°C; SizeZ_mm: 0.6; SizeX_mm: 1; SizeY_mm: 0.5; Value2: 10V; CompType: Capacitor; Cap_F: 100nF; AEC Category: Q200
C72 = CMP-0006356-2: as C39 on sheet PROC212A_USB_DC_JACK_PWR_Switch
R9 R137 = CMP-0002710-1: as R16 on sheet PROC212A_DC_Regulators
R97 R110 R164 R168 R169 R171 R174 = CMP-0002710-1: 0 Ohms Jumper Chip Resistor 0402 (1005 Metric) Automotive AEC-Q200 Thick Film; Manufacturer: Panasonic; Value: 0; SizeZ_mm: 0.4mm; AEC Qualified: Yes; AEC Grade: Grade 0; Power: 100mW
R105 R144 R149 R177 R182 = CMP-0025958-3: as R63 on sheet PROC212A_USB_DC_JACK_PWR_Switch
U16 U19 U20 = CMP-0074341-1: Automotive Catalog Dual 15-Ohm SPDT Analog Switch, DGS0010A (VSSOP-10); Alternate Manufacturer: Texas Instruments; SizeAreaWB_mm2: 23.6; U/M: EA; SizeZ_mm: 1.1; SizeX_mm: 4.9; SizeY_mm: 3.0; SizeArea_mm2: 14.7; CompType: IC
U21 = CMP-0125538-1: as U6 on sheet PROC212A_ANALOG_MUX_LVDS_DRIVER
